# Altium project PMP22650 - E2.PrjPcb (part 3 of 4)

## Sheet PMP22650 CLLLC Power Stage.SchDoc
size 431 x 279 mm; Date: Not shown in title block; ApprovedBy: Not shown in title block; CheckedBy: Not shown in title block; Author: Not shown in title block; CompanyName: Not shown in title block; Engineer: Not shown in title block; Organization: Not shown in title block; Address1: Not shown in title block; Address2: Not shown in title block; Address3: Not shown in title block; Address4: Not shown in title block; DocumentNumber: 10; Revision: Use project parameter SCH_Rev; SheetNumber: 10; SheetTotal: 16; PageSetup: Record=PageOptions¦CenterHorizontal=True¦CenterVertical=True¦PrintScale=1.00¦XCorrection=1.00¦YCorrection=1.00¦PrintKind=0¦BorderSize=5000000¦LeftOffset=0¦BottomOffset=0¦Orientation=2¦PaperLength=1000¦PaperWidth=1000¦Scale=100¦PaperSource=15¦PrintQuality=600¦MediaType=1¦DitherType=10¦PaperKind=Letter¦PrintScaleMode=1
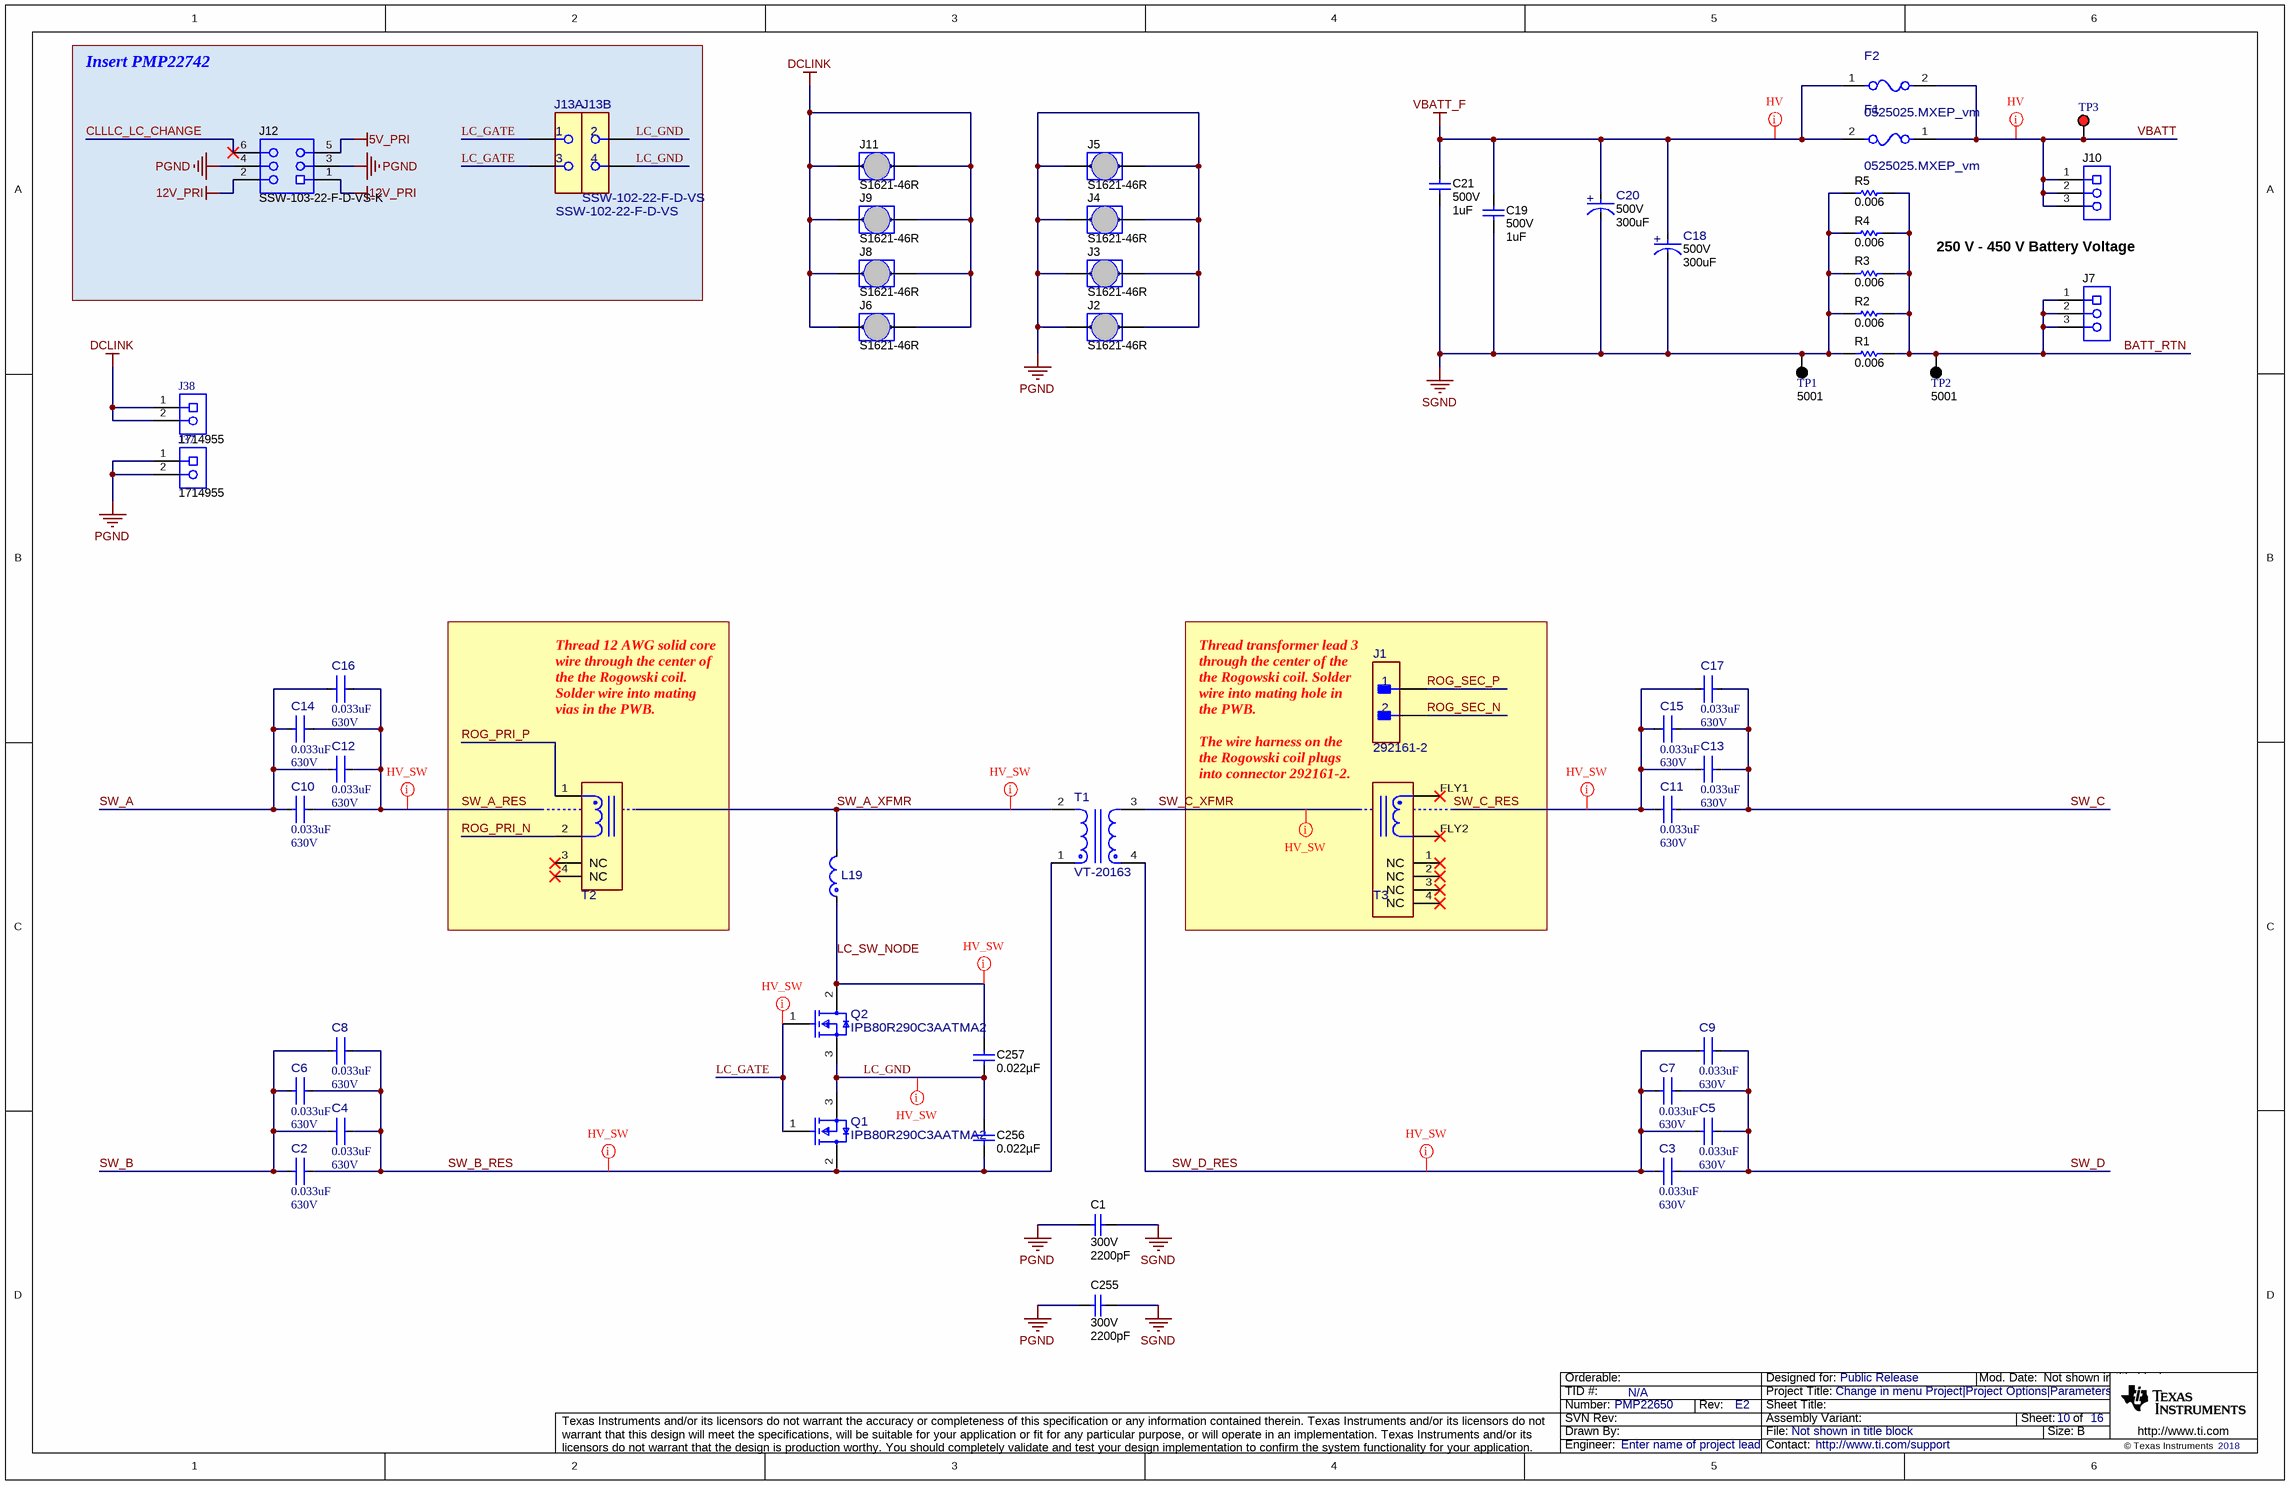
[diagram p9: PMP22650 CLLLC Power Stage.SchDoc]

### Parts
C1  VDC_V: 300V  ValueDisplayed: 2200pF  [AY2_950x500_Straight]  (hidden comment: AY2222M35Y5US63L7)
C2  ValueDisplayed: 0.033uF  VDC_V: 630V  [FP-C1210X333JBGACAUTO_1210-MFG]  (hidden comment: C1210X333JBGACAUTO)
C3  ValueDisplayed: 0.033uF  VDC_V: 630V  [FP-C1210X333JBGACAUTO_1210-MFG]  (hidden comment: C1210X333JBGACAUTO)
C4  ValueDisplayed: 0.033uF  VDC_V: 630V  [FP-C1210X333JBGACAUTO_1210-MFG]  (hidden comment: C1210X333JBGACAUTO)
C5  ValueDisplayed: 0.033uF  VDC_V: 630V  [FP-C1210X333JBGACAUTO_1210-MFG]  (hidden comment: C1210X333JBGACAUTO)
C6  ValueDisplayed: 0.033uF  VDC_V: 630V  [FP-C1210X333JBGACAUTO_1210-MFG]  (hidden comment: C1210X333JBGACAUTO)
C7  ValueDisplayed: 0.033uF  VDC_V: 630V  [FP-C1210X333JBGACAUTO_1210-MFG]  (hidden comment: C1210X333JBGACAUTO)
C8  ValueDisplayed: 0.033uF  VDC_V: 630V  [FP-C1210X333JBGACAUTO_1210-MFG]  (hidden comment: C1210X333JBGACAUTO)
C9  ValueDisplayed: 0.033uF  VDC_V: 630V  [FP-C1210X333JBGACAUTO_1210-MFG]  (hidden comment: C1210X333JBGACAUTO)
C10  ValueDisplayed: 0.033uF  VDC_V: 630V  [FP-C1210X333JBGACAUTO_1210-MFG]  (hidden comment: C1210X333JBGACAUTO)
C11  ValueDisplayed: 0.033uF  VDC_V: 630V  [FP-C1210X333JBGACAUTO_1210-MFG]  (hidden comment: C1210X333JBGACAUTO)
C12  ValueDisplayed: 0.033uF  VDC_V: 630V  [FP-C1210X333JBGACAUTO_1210-MFG]  (hidden comment: C1210X333JBGACAUTO)
C13  ValueDisplayed: 0.033uF  VDC_V: 630V  [FP-C1210X333JBGACAUTO_1210-MFG]  (hidden comment: C1210X333JBGACAUTO)
C14  ValueDisplayed: 0.033uF  VDC_V: 630V  [FP-C1210X333JBGACAUTO_1210-MFG]  (hidden comment: C1210X333JBGACAUTO)
C15  ValueDisplayed: 0.033uF  VDC_V: 630V  [FP-C1210X333JBGACAUTO_1210-MFG]  (hidden comment: C1210X333JBGACAUTO)
C16  ValueDisplayed: 0.033uF  VDC_V: 630V  [FP-C1210X333JBGACAUTO_1210-MFG]  (hidden comment: C1210X333JBGACAUTO)
C17  ValueDisplayed: 0.033uF  VDC_V: 630V  [FP-C1210X333JBGACAUTO_1210-MFG]  (hidden comment: C1210X333JBGACAUTO)
C18  VDC_V: 500V  ValueDisplayed: 300uF  [FP-ALA8DA301CF500_RADIAL-MFG]  (hidden comment: ALA8DA301CF500)
C19  VDC_V: 500V  ValueDisplayed: 1uF  [B58031I_1084x785x450]  (hidden comment: B58031I5105M002)
C20  VDC_V: 500V  ValueDisplayed: 300uF  [FP-ALA8DA301CF500_RADIAL-MFG]  (hidden comment: ALA8DA301CF500)
C21  VDC_V: 500V  ValueDisplayed: 1uF  [B58031I_1084x785x450]  (hidden comment: B58031I5105M002)
C255  VDC_V: 300V  ValueDisplayed: 2200pF  [AY2_950x500_Straight]  (hidden comment: AY2222M35Y5US63L7)
C256  ValueDisplayed: 0.022µF  [1206_190]  (hidden comment: C1206C223KDRACTU)
C257  ValueDisplayed: 0.022µF  [1206_190]  (hidden comment: C1206C223KDRACTU)
F1  0525025.MXEP_vm  [FP-0525025.MXEP_vm_AXIAL-MFG]
F2  0525025.MXEP_vm  [FP-0525025.MXEP_vm_AXIAL-MFG]
J1  292161-2  [FP-292161-2_HDR2-MFG]
J2  S1621-46R  [Harwin_S1621-46R]
J3  S1621-46R  [Harwin_S1621-46R]
J4  S1621-46R  [Harwin_S1621-46R]
J5  S1621-46R  [Harwin_S1621-46R]
J6  S1621-46R  [Harwin_S1621-46R]
J7  282856-3  [TE_282856-3]  (value not drawn)
J8  S1621-46R  [Harwin_S1621-46R]
J9  S1621-46R  [Harwin_S1621-46R]
J10  282856-3  [TE_282856-3]  (value not drawn)
J11  S1621-46R  [Harwin_S1621-46R]
J12  SSW-103-22-F-D-VS-K  [SAMTEC_SSW-103-22-F-D-VS-K]
J13  SSW-102-22-F-D-VS  [FP-SSW-102-22-F-D-VS_RCPT4-MFG]  (parts A,B of 2)
J37  1714955  [Phoenix_1714955]
J38  1714955  [Phoenix_1714955]
L19  VI-20173B  [FP-VI-20173B_PTH_INDUCTOR_34MM00_19MM00-MFG]  (value not drawn)
Q1  IPB80R290C3AATMA2  [FP-IPB80R290C3AATMA2_D2PAK-MFG]
Q2  IPB80R290C3AATMA2  [FP-IPB80R290C3AATMA2_D2PAK-MFG]
R1  ValueDisplayed: 0.006  [1206]  (hidden comment: WSL12066L000FEA18)
R2  ValueDisplayed: 0.006  [1206]  (hidden comment: WSL12066L000FEA18)
R3  ValueDisplayed: 0.006  [1206]  (hidden comment: WSL12066L000FEA18)
R4  ValueDisplayed: 0.006  [1206]  (hidden comment: WSL12066L000FEA18)
R5  ValueDisplayed: 0.006  [1206]  (hidden comment: WSL12066L000FEA18)
T1  VT-20163  [FP-VT-20163_PTH_TRANSFORMER_73MM0_51MM0-MFG]
T2  RLTI-1371  [FP-RLTI-1371_PTH_XFRMR_0IN828_0IN300-MFG]  (value not drawn)
T3  RLTI-1379  [FP-RLTI-1379_PTH_XFRMR_0IN828_0IN300-MFG]  (value not drawn)
TP1  5001  [Keystone5001]
TP2  5001  [Keystone5001]
TP3  5000  [Keystone5000]  (value not drawn)

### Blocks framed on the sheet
Insert PMP22742: J12 J13

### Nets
5V_PRI: J12.5
12V_PRI: J12.1 J12.2
DCLINK: J6.1 J6.2 J8.1 J8.2 J9.1 J9.2 J11.1 J11.2 J38.1 J38.2
PGND: C1.2 C255.2 J2.1 J2.2 J3.1 J3.2 J4.1 J4.2 J5.1 J5.2 J12.3 J12.4 J37.1 J37.2
SGND: C1.1 C18.1(CATHODE) C19.2 C20.1(CATHODE) C21.2 C255.1 R1.1 R2.1 R3.1 R4.1 R5.1 TP1.1
VBATT_F: C18.2(ANODE) C19.1 C20.2(ANODE) C21.1 F1.2 F2.1
BATT_RTN: J7.1 J7.2 J7.3 R1.2 R2.2 R3.2 R4.2 R5.2 TP2.1
CLLLC_LC_CHANGE: J12.6
LC_GATE: J13.1 J13.3 Q1.1(GATE) Q2.1(GATE)
LC_GND: C256.1 C257.2 J13.2 J13.4 Q1.3(SOURCE) Q2.3(SOURCE)
LC_SW_NODE: C257.1 L19.1 Q2.2(DRAIN)
ROG_PRI_N: T2.2
ROG_PRI_P: T2.1
ROG_SEC_N: J1.2
ROG_SEC_P: J1.1
SW_A: C10.2 C12.2 C14.2 C16.2
SW_A_RES: C10.1 C12.1 C14.1 C16.1
SW_A_XFMR: L19.2 T1.2
SW_B: C2.2 C4.2 C6.2 C8.2
SW_B_RES: C2.1 C4.1 C6.1 C8.1 C256.2 Q1.2(DRAIN) T1.1
SW_C: C11.2 C13.2 C15.2 C17.2
SW_C_RES: C11.1 C13.1 C15.1 C17.1
SW_C_XFMR: T1.3
SW_D: C3.1 C5.1 C7.1 C9.1
SW_D_RES: C3.2 C5.2 C7.2 C9.2 T1.4
VBATT: F1.1 F2.2 J10.1 J10.2 J10.3 TP3.1

Not connected (* = marked no-connect by the designer): T2 3(NC)* 4(NC)*; T3 1(NC)* 2(NC)* 3(NC)* 4(NC)*

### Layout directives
net class HV: VBATT, VBATT_F
net class HV_SW: LC_GATE, LC_GND, LC_SW_NODE, SW_A_RES, SW_A_XFMR, SW_B_RES, SW_C_RES, SW_C_XFMR, SW_D_RES

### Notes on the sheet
- 250 V - 450 V Battery Voltage
- Thread 12 AWG solid core wire through the center of the the Rogowski coil. Solder wire into mating vias in the PWB.
- (near J1) Thread transformer lead 3 through the center of the the Rogowski coil. Solder wire into mating hole in the PWB.
  The wire harness on the the Rogowski coil plugs into connector 292161-2.

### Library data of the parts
C1 C255 = CMP-0009587-2: CAP, CERM, 2200 pF, 300 V, +/- 20%, Y5U, AEC-Q200 Grade 1, D9.5xT5mm; Manufacturer: Vishay-Bccomponents; TaMin_C: -55°C; Polarized: N; SizeAreaWB_mm2: 80.5; Value1: Unknown; U/M: EA; Value: 2200pF; TaMax_C: 125°C; SizeZ_mm: 14.5; SizeX_mm: 9.5; SizeY_mm: 5; Cap_Case: 9.5x5mm; SizeArea_mm2: 47.5; AEC Qualified: Y; Cap_F: 2.2nF; AEC Grade: 1; AEC Category: Q200
C2-C17 = CMP-0090696-1: 0.033µF ±5% 630V Ceramic Capacitor C0G, NP0 1210 (3225 Metric); Manufacturer: Kemet; Cap_F: 33nF; SizeZ_mm: 2.8mm; TempCo: 30ppm/°C; AEC Qualified: Yes; Value: 33nF; AEC Grade: Grade 1
C18 C20 = CMP-0090464-1: 300µF 500V Aluminum Electrolytic Capacitors Radial, Can - Snap-In 687.4mOhm @ 100Hz 7000 Hrs @ 105°C; Manufacturer: Kemet; Tolerance_%: 20%; AEC Qualified: Yes; Esr: 0.687; Leakage Current: 450uA; Life: 11000Hours; AEC Grade: Grade 2; SizeZ_mm: 52mm; IRMS_A: 4.8A
C19 C21 = CMP-0009311-2: CAP, CERM, 1 uF, 500 V, +/- 20%, B58031, AEC-Q200 Grade 0, 6.84x7.85mm; Manufacturer: TDK; PartNumber: B58031I5105M062; TaMin_C: -40°C; Polarized: N; SizeAreaWB_mm2: 126.474; Value1: Unknown; U/M: EA; Value: 1uF; TaMax_C: 150°C; SizeZ_mm: 4.5; SizeX_mm: 10.84; SizeY_mm: 7.85; Cap_Case: 10.84x7.85x4.5mm; SizeArea_mm2: 85.094; CompType: Capacitor; AEC Qualified: Y; Cap_F: 1µF; IRMS_A: 7.5A; AEC Grade: 0; AEC Category: Q200
C256 C257 = CMP-0084048-1: CAP, CERM, 0.022 µF, 1000 V,+/- 10%, X7R, AEC-Q200 Grade 1, 1206; Manufacturer: Kemet; Polarized: N; CompType: Capacitor; Value: 0.022uF; U/M: EA; Cap_F: 22nF; VDC_V: 1kV; Value2: 1000V; TaMin_C: -55°C; TaMax_C: 125°C; Cap_Case: 1206; SizeArea_mm2: 5.12; SizeAreaWB_mm2: 10.92; SizeX_mm: 3.2; SizeY_mm: 1.6; SizeZ_mm: 1.9; AEC Category: Q200; AEC Qualified: Y; AEC Grade: 1
F1 F2 = CMP-4956-0000-1: 25A AC 450V DC Fuse Cartridge, Ceramic Through Hole 3AB, 3AG, 1/4" x 1-1/4" (Axial); Manufacturer: Littelfuse; AEC Grade: NA; Fuse Interrupt Dc Current: 10000A; AEC Qualified: No; Res_ohm: 3.8mΩ; MeltingTyp: 320A2Sec; Interrupt_DC: 10kA
J1 = CMP-0090793-1: Connector Header Through Hole 2 position 0.079" (2.00mm); Manufacturer: TE Connectivity; Current_A: 4A; Conn Orientation: Vertical; SizeZ_mm: 7mm; Conn Gender: Male; Row_Count: 1; DUT-Pitch_mm: 2mm; Voltage_V: 125V; ContactFinish: Tin,Nickel; AEC Qualified: No
J2-J6 J8 J9 J11 = CMP-0075177-1: JUMPER TIN SMD, SMT; Manufacturer: Harwin; CNHeader: False; Current_A: 10A; Green_Lifecycle: Active; Green_REACh: Passed; CompType: Jumper Wire
J7 J10 = CMP-0054983-1: Receptacle, 3x1, 5mm, R/A, TH; Manufacturer: On Shore Technology Inc.; PartNumber: ED700/3; CNHeader: FALSE; Current_A: 24A; Gender: Female; Voltage_V: 300V; CompType: Terminal Block; Row_Count: 1; Pitch_mm: 5; ContactFinish: Tin; CT: TRUE; Cert_UL: Y
J12 = CMP-0055666-1: Receptacle, 2.54mm, 3x2, Tin, SMT; Manufacturer: Samtec; CNHeader: FALSE; Current_A: 5.7A; Gender: Female; CompType: Socket Strip; Row_Count: 2; RowSpacing_mm: 2.54; ContactFinish: Gold; CT: TRUE; Cert_UL: Y
J13 = CMP-0090790-1: 4 Position Receptacle Connector  Surface Mount; Manufacturer: Samtec; Conn Gender: Female; SizeZ_mm: 10.21mm; DUT-Pitch_mm: 2.54mm; Is Female: yes; Voltage_V: 655V; Current_A: 4.7A; Row_Count: 2; AEC Qualified: No; ContactFinish: Gold,Nickel; Standoff Height: 0.97mm; Conn Orientation: Vertical
J37 J38 = CMP-0055505-1: Terminal Block, 2x1, 6.35mm, Green, TH; Manufacturer: Phoenix Contact; CNHeader: FALSE; Shrouded: Y; Gender: Female; Row_Count: 1; Pitch_mm: 6.35; CT: TRUE
L19 = CMP-0090978-1: OBC Resonant Inductor; Manufacturer: Cyntec; Ind_H: 50µH; Value: 50uH; Test Frequency: 500kHz; AEC Qualified: No; DCR_ohm: 69m
Q1 Q2 = CMP-0090447-1: N-Channel 800V 17A (Tc) 227W (Tc) Surface Mount PG-TO263-3-2; Manufacturer: Infineon Technologies; VdsMax_V: 1.2V; Reverse Recovery Time: 550ns; AEC Qualified: Yes; Number Of Channels: 1; Input Capacitace At Vds: 2300pF @ 100V; Turn Off Delay Time: 72ns; Rdson45_ohm: 0.25; Turn On Delay Time: 25ns; Threshold Vgs Max: 3.9V; Rthja Max: 62K/W; QgTyp_nC: 88nC @ 10V; Vgs_V: 20V; TJmax_C: +150°C; Pulse Drain Current: 51A; AEC Grade: Grade 0; Standoff Height: 0mm; Typ Forward Diode Voltage: 1V; Threshold Vgs Min: 2.1V; Reverse Recovery Charge: 15000nC; ChMode: False; SizeZ_mm: 4.7mm
R1-R5 = CMP-0018567-2: RES, 0.006, 1%, 0.5 W, 1206; Manufacturer: Vishay-Dale; Power_W: 500mW; TempCo: 110 ppm/C; Value_Code: 6L000; U/M: EA; Value: 0.006; EIA_Code: E96; Res_ohm: 6m; SizeX_mm: 3.2; SizeY_mm: 1.6; SizeZ_mm: 1.35; Value2: 0.5W; SizeArea_mm2: 5.12; AEC Category: Q200
T1 = CMP-0090781-3: TRANSFORMER; Manufacturer: Cyntec; DCR_ohm: 9.6m; Ind_H: 16µH; Voltage_Isolation_Vrms: 2000VDC; Rsec1_ohm: 7.4m; AEC Qualified: Unknown
T2 = CMP-0090959-1: PRIMARY SIDE ROGOWSKI (PMP22495); Manufacturer: Renco Electronics; SizeZ_mm: 0.938inch; AEC Qualified: No; Ind_H: 6.3µH; DCR_ohm: 1.2
T3 = CMP-0090960-2: Secondary Side Rogowski (PMP22495); Manufacturer: Renco Electronics; AEC Qualified: No; Ind_H: 6.3µH; SizeZ_mm: 0.938inch; DCR_ohm: 1.2
TP1 TP2 = CMP-0055138-1: Test Point, Miniature, Black, TH; Manufacturer: Keystone; CNHeader: FALSE; Green_Lifecycle: Active; Green_REACh: Passed; ContactFinish: Silver; CT: TRUE
TP3 = CMP-0055137-1: Test Point, Miniature, Red, TH; Manufacturer: Keystone; CNHeader: FALSE; Green_Lifecycle: Active; Green_REACh: Passed; ContactFinish: Silver; CT: TRUE

## Sheet PMP22650 CLLLC GaN Phase A.SchDoc
size 431 x 279 mm; Date: Not shown in title block; ApprovedBy: Not shown in title block; CheckedBy: Not shown in title block; Author: Not shown in title block; CompanyName: Not shown in title block; Engineer: Not shown in title block; Organization: Not shown in title block; Address1: Not shown in title block; Address2: Not shown in title block; Address3: Not shown in title block; Address4: Not shown in title block; DocumentNumber: 11; Revision: Use project parameter SCH_Rev; SheetNumber: 11; SheetTotal: 16; PageSetup: Record=PageOptions¦CenterHorizontal=True¦CenterVertical=True¦PrintScale=1.00¦XCorrection=1.00¦YCorrection=1.00¦PrintKind=0¦BorderSize=5000000¦LeftOffset=0¦BottomOffset=0¦Orientation=2¦PaperLength=1000¦PaperWidth=1000¦Scale=100¦PaperSource=15¦PrintQuality=600¦MediaType=1¦DitherType=10¦PaperKind=Letter¦PrintScaleMode=1
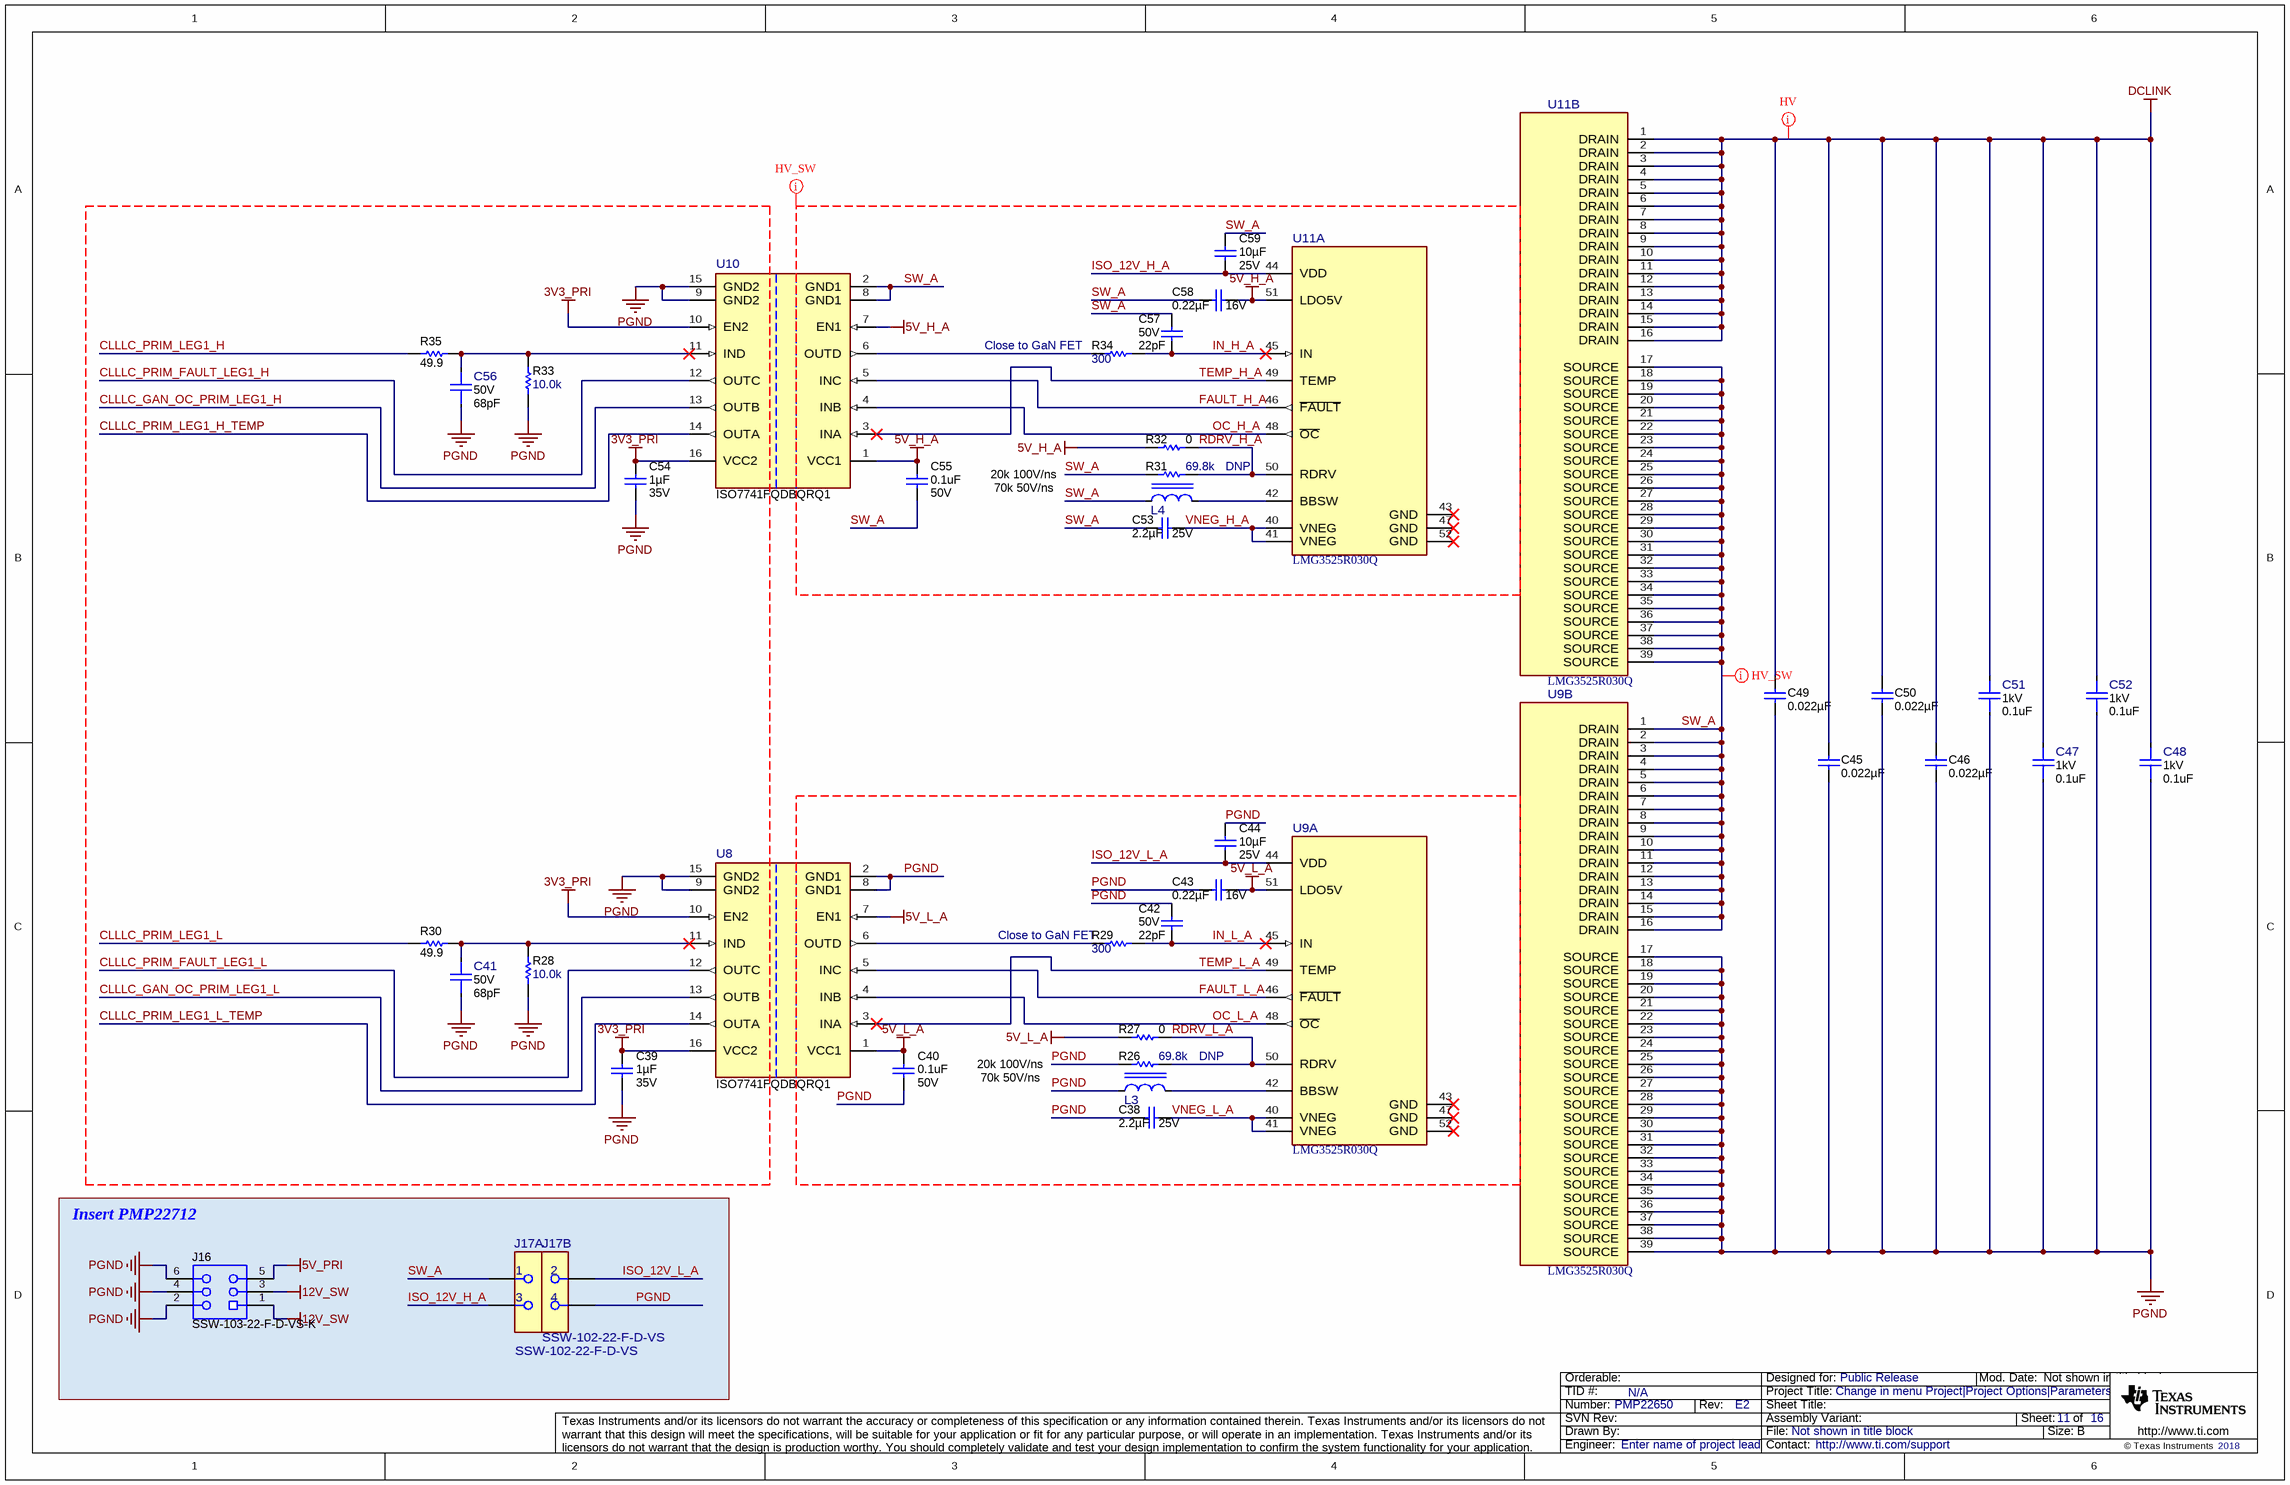
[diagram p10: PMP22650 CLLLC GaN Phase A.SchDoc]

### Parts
C38  Cap_F: 2.2µF  VDC_V: 25V  [0805_HV]  (hidden comment: CGA4J3X7R1E225K125AB)
C39  VDC_V: 35V  ValueDisplayed: 1µF  [0402]  (hidden comment: GRT155R6YA105KE13D)
C40  VDC_V: 50V  ValueDisplayed: 0.1uF  [0402]  (hidden comment: GCM155R71H104KE02D)
C41  VDC_V: 50V  ValueDisplayed: 68pF  [FP-GCM1555C1H680JA16D_0402-MFG]  (hidden comment: GCM1555C1H680JA16D)
C42  VDC_V: 50V  ValueDisplayed: 22pF  [0402]  (hidden comment: GCM1555C1H220JA16D)
C43  VDC_V: 16V  ValueDisplayed: 0.22µF  [0402]  (hidden comment: GCM155R71C224KE02D)
C44  VDC_V: 25V  ValueDisplayed: 10µF  [1206_180]  (hidden comment: TMK316AB7106KLHT)
C45  ValueDisplayed: 0.022µF  [1206_190]  (hidden comment: C1206C223KDRACTU)
C46  ValueDisplayed: 0.022µF  [1206_190]  (hidden comment: C1206C223KDRACTU)
C47  VDC_V: 1kV  ValueDisplayed: 0.1uF  [FP-C1812X104KDRACAUTO_1812-MFG]  (hidden comment: C1812X104KDRACAUTO)
C48  VDC_V: 1kV  ValueDisplayed: 0.1uF  [FP-C1812X104KDRACAUTO_1812-MFG]  (hidden comment: C1812X104KDRACAUTO)
C49  ValueDisplayed: 0.022µF  [1206_190]  (hidden comment: C1206C223KDRACTU)
C50  ValueDisplayed: 0.022µF  [1206_190]  (hidden comment: C1206C223KDRACTU)
C51  VDC_V: 1kV  ValueDisplayed: 0.1uF  [FP-C1812X104KDRACAUTO_1812-MFG]  (hidden comment: C1812X104KDRACAUTO)
C52  VDC_V: 1kV  ValueDisplayed: 0.1uF  [FP-C1812X104KDRACAUTO_1812-MFG]  (hidden comment: C1812X104KDRACAUTO)
C53  Cap_F: 2.2µF  VDC_V: 25V  [0805_HV]  (hidden comment: CGA4J3X7R1E225K125AB)
C54  VDC_V: 35V  ValueDisplayed: 1µF  [0402]  (hidden comment: GRT155R6YA105KE13D)
C55  VDC_V: 50V  ValueDisplayed: 0.1uF  [0402]  (hidden comment: GCM155R71H104KE02D)
C56  VDC_V: 50V  ValueDisplayed: 68pF  [FP-GCM1555C1H680JA16D_0402-MFG]  (hidden comment: GCM1555C1H680JA16D)
C57  VDC_V: 50V  ValueDisplayed: 22pF  [0402]  (hidden comment: GCM1555C1H220JA16D)
C58  VDC_V: 16V  ValueDisplayed: 0.22µF  [0402]  (hidden comment: GCM155R71C224KE02D)
C59  VDC_V: 25V  ValueDisplayed: 10µF  [1206_180]  (hidden comment: TMK316AB7106KLHT)
J16  SSW-103-22-F-D-VS-K  [SAMTEC_SSW-103-22-F-D-VS-K]
J17  SSW-102-22-F-D-VS  [FP-SSW-102-22-F-D-VS_RCPT4-MFG]  (parts A,B of 2)
L3  MPIA2510V2-4R7-R  [FP-MPIA2510V2-4R7-R_1008-MFG]  (value not drawn)
L4  MPIA2510V2-4R7-R  [FP-MPIA2510V2-4R7-R_1008-MFG]  (value not drawn)
R26  ValueDisplayed: 69.8k  [0402]  (hidden comment: CRCW040269K8FKED)
R27  ValueDisplayed: 0  [0402]  (hidden comment: ERJ-2GE0R00X)
R28  ValueDisplayed: 10.0k  [0402]  (hidden comment: CRCW040210K0FKED)
R29  ValueDisplayed: 300  [0402]  (hidden comment: CRCW0402300RJNED)
R30  ValueDisplayed: 49.9  [0402]  (hidden comment: CRCW040249R9FKED)
R31  ValueDisplayed: 69.8k  [0402]  (hidden comment: CRCW040269K8FKED)
R32  ValueDisplayed: 0  [0402]  (hidden comment: ERJ-2GE0R00X)
R33  ValueDisplayed: 10.0k  [0402]  (hidden comment: CRCW040210K0FKED)
R34  ValueDisplayed: 300  [0402]  (hidden comment: CRCW0402300RJNED)
R35  ValueDisplayed: 49.9  [0402]  (hidden comment: CRCW040249R9FKED)
U8  ISO7741FQDBQRQ1  [DBQ0016A-MFG]
U9  LMG3525R030Q  [RQS0052A-MFG]  (parts A,B of 2)
U10  ISO7741FQDBQRQ1  [DBQ0016A-MFG]
U11  LMG3525R030Q  [RQS0052A-MFG]  (parts A,B of 2)

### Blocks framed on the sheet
Insert PMP22712: J16 J17

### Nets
3V3_PRI: C39.1 C54.1 U8.10(EN2) U8.16(VCC2) U10.10(EN2) U10.16(VCC2)
5V_H_A: C55.1 C58.1 R32.2 U10.1(VCC1) U10.7(EN1) U11.51(LDO5V)
5V_L_A: C40.1 C43.1 R27.2 U8.1(VCC1) U8.7(EN1) U9.51(LDO5V)
5V_PRI: J16.5
12V_SW: J16.1 J16.3
DCLINK: C45.1 C46.1 C47.2 C48.2 C49.1 C50.1 C51.2 C52.2 U11.1(DRAIN) U11.2(DRAIN) U11.3(DRAIN) U11.4(DRAIN) U11.5(DRAIN) U11.6(DRAIN) U11.7(DRAIN) U11.8(DRAIN) U11.9(DRAIN) U11.10(DRAIN) U11.11(DRAIN) U11.12(DRAIN) U11.13(DRAIN) U11.14(DRAIN) U11.15(DRAIN) U11.16(DRAIN)
PGND: C38.1 C39.2 C40.2 C41.1 C42.1 C43.2 C44.2 C45.2 C46.2 C47.1 C48.1 C49.2 C50.2 C51.1 C52.1 C54.2 C56.1 J16.2 J16.4 J16.6 J17.4 L3.1 R26.1 R28.1 R33.1 U8.2(GND1) U8.8(GND1) U8.9(GND2) U8.15(GND2) U9.17(SOURCE) U9.18(SOURCE) U9.19(SOURCE) U9.20(SOURCE) U9.21(SOURCE) U9.22(SOURCE) U9.23(SOURCE) U9.24(SOURCE) U9.25(SOURCE) U9.26(SOURCE) U9.27(SOURCE) U9.28(SOURCE) U9.29(SOURCE) U9.30(SOURCE) U9.31(SOURCE) U9.32(SOURCE) U9.33(SOURCE) U9.34(SOURCE) U9.35(SOURCE) U9.36(SOURCE) U9.37(SOURCE) U9.38(SOURCE) U9.39(SOURCE) U10.9(GND2) U10.15(GND2)
CLLLC_GAN_OC_PRIM_LEG1_H: U10.13(OUTB)
CLLLC_GAN_OC_PRIM_LEG1_L: U8.13(OUTB)
CLLLC_PRIM_FAULT_LEG1_H: U10.12(OUTC)
CLLLC_PRIM_FAULT_LEG1_L: U8.12(OUTC)
CLLLC_PRIM_LEG1_H: R35.1
CLLLC_PRIM_LEG1_H_TEMP: U10.14(OUTA)
CLLLC_PRIM_LEG1_L: R30.1
CLLLC_PRIM_LEG1_L_TEMP: U8.14(OUTA)
FAULT_H_A: U10.5(INC) U11.46(~{FAULT})
FAULT_L_A: U8.5(INC) U9.46(~{FAULT})
IN_H_A: C57.2 R34.2 U11.45(IN)
IN_L_A: C42.2 R29.2 U9.45(IN)
ISO_12V_H_A: C59.1 J17.3 U11.44(VDD)
ISO_12V_L_A: C44.1 J17.2 U9.44(VDD)
OC_H_A: U10.4(INB) U11.48(~{OC})
OC_L_A: U8.4(INB) U9.48(~{OC})
RDRV_H_A: R31.2 R32.1 U11.50(RDRV)
RDRV_L_A: R26.2 R27.1 U9.50(RDRV)
SW_A: C53.1 C55.2 C57.1 C58.2 C59.2 J17.1 L4.1 R31.1 U9.1(DRAIN) U9.2(DRAIN) U9.3(DRAIN) U9.4(DRAIN) U9.5(DRAIN) U9.6(DRAIN) U9.7(DRAIN) U9.8(DRAIN) U9.9(DRAIN) U9.10(DRAIN) U9.11(DRAIN) U9.12(DRAIN) U9.13(DRAIN) U9.14(DRAIN) U9.15(DRAIN) U9.16(DRAIN) U10.2(GND1) U10.8(GND1) U11.17(SOURCE) U11.18(SOURCE) U11.19(SOURCE) U11.20(SOURCE) U11.21(SOURCE) U11.22(SOURCE) U11.23(SOURCE) U11.24(SOURCE) U11.25(SOURCE) U11.26(SOURCE) U11.27(SOURCE) U11.28(SOURCE) U11.29(SOURCE) U11.30(SOURCE) U11.31(SOURCE) U11.32(SOURCE) U11.33(SOURCE) U11.34(SOURCE) U11.35(SOURCE) U11.36(SOURCE) U11.37(SOURCE) U11.38(SOURCE) U11.39(SOURCE)
TEMP_H_A: U10.3(INA) U11.49(TEMP)
TEMP_L_A: U8.3(INA) U9.49(TEMP)
VNEG_H_A: C53.2 U11.40(VNEG) U11.41(VNEG)
VNEG_L_A: C38.2 U9.40(VNEG) U9.41(VNEG)
NetC41_2: C41.2 R28.2 R30.2 U8.11(IND)
NetC56_2: C56.2 R33.2 R35.2 U10.11(IND)
NetL3_2: L3.2 U9.42(BBSW)
NetL4_2: L4.2 U11.42(BBSW)
NetR29_1: R29.1 U8.6(OUTD)
NetR34_1: R34.1 U10.6(OUTD)

Not connected (* = marked no-connect by the designer): U9 43(GND)* 47(GND)* 52(GND)*; U11 43(GND)* 47(GND)* 52(GND)*

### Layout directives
net class HV_SW: 5V_H_A, FAULT_H_A, IN_H_A, ISO_12V_H_A, OC_H_A, RDRV_H_A, SW_A, TEMP_H_A, VNEG_H_A
net class HV: DCLINK

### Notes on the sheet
- (near R34) Close to GaN FET
- 20k 100V/ns
- 70k 50V/ns
- DNP
- (near R29) Close to GaN FET

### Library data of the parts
C38 C53 = CMP-0007975-2: CAP, CERM, 2.2 uF, 25 V, +/- 10%, X7R, AEC-Q200 Grade 1, 0805; Manufacturer: TDK; TaMin_C: -55°C; Polarized: N; SizeAreaWB_mm2: 6.75; Value1: Unknown; U/M: EA; Value: 2.2uF; TaMax_C: 125°C; SizeZ_mm: 1.45; SizeX_mm: 2; SizeY_mm: 1.25; Cap_Case: 0805; SizeArea_mm2: 2.5; AEC Qualified: Y; AEC Grade: 1; AEC Category: Q200
C39 C54 = CMP-0750099-1: CAP, CERM, 1 µF, 35 V,+/- 10%, X5R, AEC-Q200 Grade 3, 0402; Manufacturer: MuRata; AEC Grade: 3; AEC Category: Q200; Value: 1uF; SizeArea_mm2: 0.5; SizeZ_mm: 0.6; AEC Qualified: Y; TaMin_C: -55°C; SizeX_mm: 1; U/M: EA; Polarized: N; TaMax_C: 85°C
C40 C55 = CMP-0006356-2: CAP, CERM, 0.1 uF, 50 V, +/- 10%, X7R, AEC-Q200 Grade 1, 0402; Manufacturer: MuRata; TaMin_C: -55°C; Polarized: N; SizeAreaWB_mm2: 3; Value1: Unknown; U/M: EA; Value: 0.1uF; TaMax_C: 125°C; SizeZ_mm: 0.6; SizeX_mm: 1; SizeY_mm: 0.5; AEC Qualified: Y; Cap_F: 100nF; AEC Category: Q200
C41 C56 = CMP-0090521-1: 68pF ±5% 50V Ceramic Capacitor C0G, NP0 0402 (1005 Metric); Manufacturer: Murata; AEC Qualified: Yes; AEC Grade: Grade 1; TempCo: 30ppm/°C; SizeZ_mm: 0.55mm
C42 C57 = CMP-0006348-2: CAP, CERM, 22 pF, 50 V, +/- 5%, C0G/NP0, AEC-Q200 Grade 1, 0402; Manufacturer: MuRata; TaMin_C: -55°C; Polarized: N; SizeAreaWB_mm2: 3; Value1: Unknown; U/M: EA; Value: 22pF; TaMax_C: 125°C; SizeZ_mm: 0.6; SizeX_mm: 1; SizeY_mm: 0.5; AEC Qualified: Y; AEC Category: Q200
C43 C58 = CMP-0078265-1: CAP, CERM, 0.22 µF, 16 V,+/- 10%, X7R, AEC-Q200 Grade 1, 0402; Manufacturer: MuRata; TaMin_C: -55°C; Polarized: N; SizeAreaWB_mm2: 3; U/M: EA; Value: 0.22uF; TaMax_C: 125°C; SizeZ_mm: 0.6; SizeX_mm: 1; SizeY_mm: 0.5; AEC Qualified: Y; Cap_F: 220nF; AEC Category: Q200
C44 C59 = CMP-0750154-1: CAP, CERM, 10 µF, 25 V,+/- 10%, X7R, AEC-Q200 Grade 1, 1206; Manufacturer: Taiyo Yuden; AEC Qualified: Y; SizeZ_mm: 1.8; TaMax_C: 125°C; TaMin_C: -55°C; Cap_Case: 1206; Polarized: N; AEC Grade: 1; SizeY_mm: 1.6; Value: 10uF; SizeX_mm: 3.2; SizeAreaWB_mm2: 10.92; AEC Category: Q200; U/M: EA; SizeArea_mm2: 5.12
C45 C46 C49 C50 = CMP-0084048-1: as C256 on sheet PMP22650 CLLLC Power Stage
C47 C48 C51 C52 = CMP-0090548-1: 0.1µF ±10% 1000V (1kV) Ceramic Capacitor X7R 1812 (4532 Metric); Manufacturer: Kemet; SizeZ_mm: 1.85mm; AEC Qualified: Yes; Cap_F: 100nF; TempCo: 15%; Value: 100nF; AEC Grade: Grade 1
J16 = CMP-0055666-1: as J12 on sheet PMP22650 CLLLC Power Stage
J17 = CMP-0090790-1: 4 Position Receptacle Connector  Surface Mount; Manufacturer: Samtec; DUT-Pitch_mm: 2.54mm; SizeZ_mm: 10.21mm; Current_A: 4.7A; ContactFinish: Gold,Nickel; Conn Gender: Female; Voltage_V: 655V; Is Female: yes; AEC Qualified: No; Row_Count: 2; Conn Orientation: Vertical; Standoff Height: 0.97mm
L3 L4 = CMP-0090507-1: 4.7µH Shielded Molded Inductor 1.22A 262mOhm Max 1008 (2520 Metric); Manufacturer: Eaton; Material: Metal Composite; Value: 4.7uH; Test Frequency: 1MHz; Isat: 1.8A; DCR_ohm: 0.262; AEC Grade: Grade 1; Tolerance_%: 20%; AEC Qualified: Yes; Self Resonant Frequency: 25MHz; SizeZ_mm: 1.05mm; Shrouded: true
R26 R31 = CMP-0026510-2: RES, 69.8 k, 1%, 0.063 W, AEC-Q200 Grade 0, 0402; Manufacturer: Vishay-Dale; Power_W: 63mW; TempCo: 100 ppm/C; Value_Code: 69k8; Value: 69.8k; EIA_Code: E96; SizeX_mm: 1; SizeY_mm: 0.5; SizeZ_mm: 0.6; Value2: 0.063W; AEC Qualified: Y; VDC_V: 50V; AEC Category: Q200; AEC Grade: 0
R27 R32 = CMP-0026992-3: RES, 0, 5%, 0.1 W, AEC-Q200 Grade 0, 0402; Manufacturer: Panasonic; Power_W: 100mW; TempCo: 600 ppm/C; Value_Code: 0000; Value: 0; EIA_Code: E24; SizeX_mm: 1; SizeY_mm: 0.5; SizeZ_mm: 0.6; Value2: 0.1W; AEC Qualified: Y; VDC_V: 50V; AEC Category: Q200; SizeAreaWB_mm2: 3
R28 R33 = CMP-0025958-3: RES, 10.0 k, 1%, 0.063 W, AEC-Q200 Grade 0, 0402; Manufacturer: Vishay-Dale; Power_W: 63mW; TempCo: 100 ppm/C; Value_Code: 10k0; Value: 10.0k; EIA_Code: E96; Res_ohm: 10k; SizeX_mm: 1; SizeY_mm: 0.5; SizeZ_mm: 0.6; Value2: 0.063W; AEC Qualified: Y; VDC_V: 50V; AEC Category: Q200; AEC Grade: 0
R29 R34 = CMP-0026902-3: RES, 300, 5%, 0.063 W, AEC-Q200 Grade 0, 0402; Manufacturer: Vishay-Dale; Power_W: 63mW; TempCo: 200 ppm/C; Value_Code: 300R; Value: 300; EIA_Code: E24; SizeX_mm: 1; SizeY_mm: 0.5; SizeZ_mm: 0.6; Value2: 0.063W; AEC Qualified: Y; VDC_V: 50V; AEC Category: Q200; AEC Grade: 0
R30 R35 = CMP-0026404-2: RES, 49.9, 1%, 0.063 W, AEC-Q200 Grade 0, 0402; Manufacturer: Vishay-Dale; Power_W: 63mW; TempCo: 100 ppm/C; Value_Code: 49R9; Value: 49.9; EIA_Code: E96; SizeX_mm: 1; SizeY_mm: 0.5; SizeZ_mm: 0.6; Value2: 0.063W; AEC Qualified: Y; VDC_V: 50V; AEC Category: Q200; AEC Grade: 0
U8 U10 = CMP-0090469-1: Manufacturer: Texas Instruments; TaMin_C: -40°C; TaMax_C: +125°C; TJmax_C: +150°C; AEC Grade: Grade 1; Min Supply Voltage: 2.25V; AEC Qualified: Yes; Max Supply Voltage: 5.5V; Standoff Height: 0.11mm; Nominal Supply Current: 1.5-18mA; SizeZ_mm: 1.75mm
U9 U11 = CMP-0089968-2: 650-V 30-mΩ GaN FET with Integrated Driver and Protection; Manufacturer: Texas Instruments; Output Voltage: 520V; Nominal Supply Current: 540uA; Min Supply Voltage: 7.5V; Standoff Height: 0mm; AEC Grade: Grade 1; Max Supply Voltage: 18V; Number Of Outputs: 1; AEC Qualified: Yes; TJmax_C: +125°C; SizeZ_mm: 1mm; AEC Category: Q200; CompType: IC

## Sheet PMP22650 CLLLC GaN Phase B.SchDoc
size 431 x 279 mm; Date: Not shown in title block; ApprovedBy: Not shown in title block; CheckedBy: Not shown in title block; Author: Not shown in title block; CompanyName: Not shown in title block; Engineer: Not shown in title block; Organization: Not shown in title block; Address1: Not shown in title block; Address2: Not shown in title block; Address3: Not shown in title block; Address4: Not shown in title block; DocumentNumber: 12; Revision: Use project parameter SCH_Rev; SheetNumber: 12; SheetTotal: 16; PageSetup: Record=PageOptions¦CenterHorizontal=True¦CenterVertical=True¦PrintScale=1.00¦XCorrection=1.00¦YCorrection=1.00¦PrintKind=0¦BorderSize=5000000¦LeftOffset=0¦BottomOffset=0¦Orientation=2¦PaperLength=1000¦PaperWidth=1000¦Scale=100¦PaperSource=15¦PrintQuality=600¦MediaType=1¦DitherType=10¦PaperKind=Letter¦PrintScaleMode=1
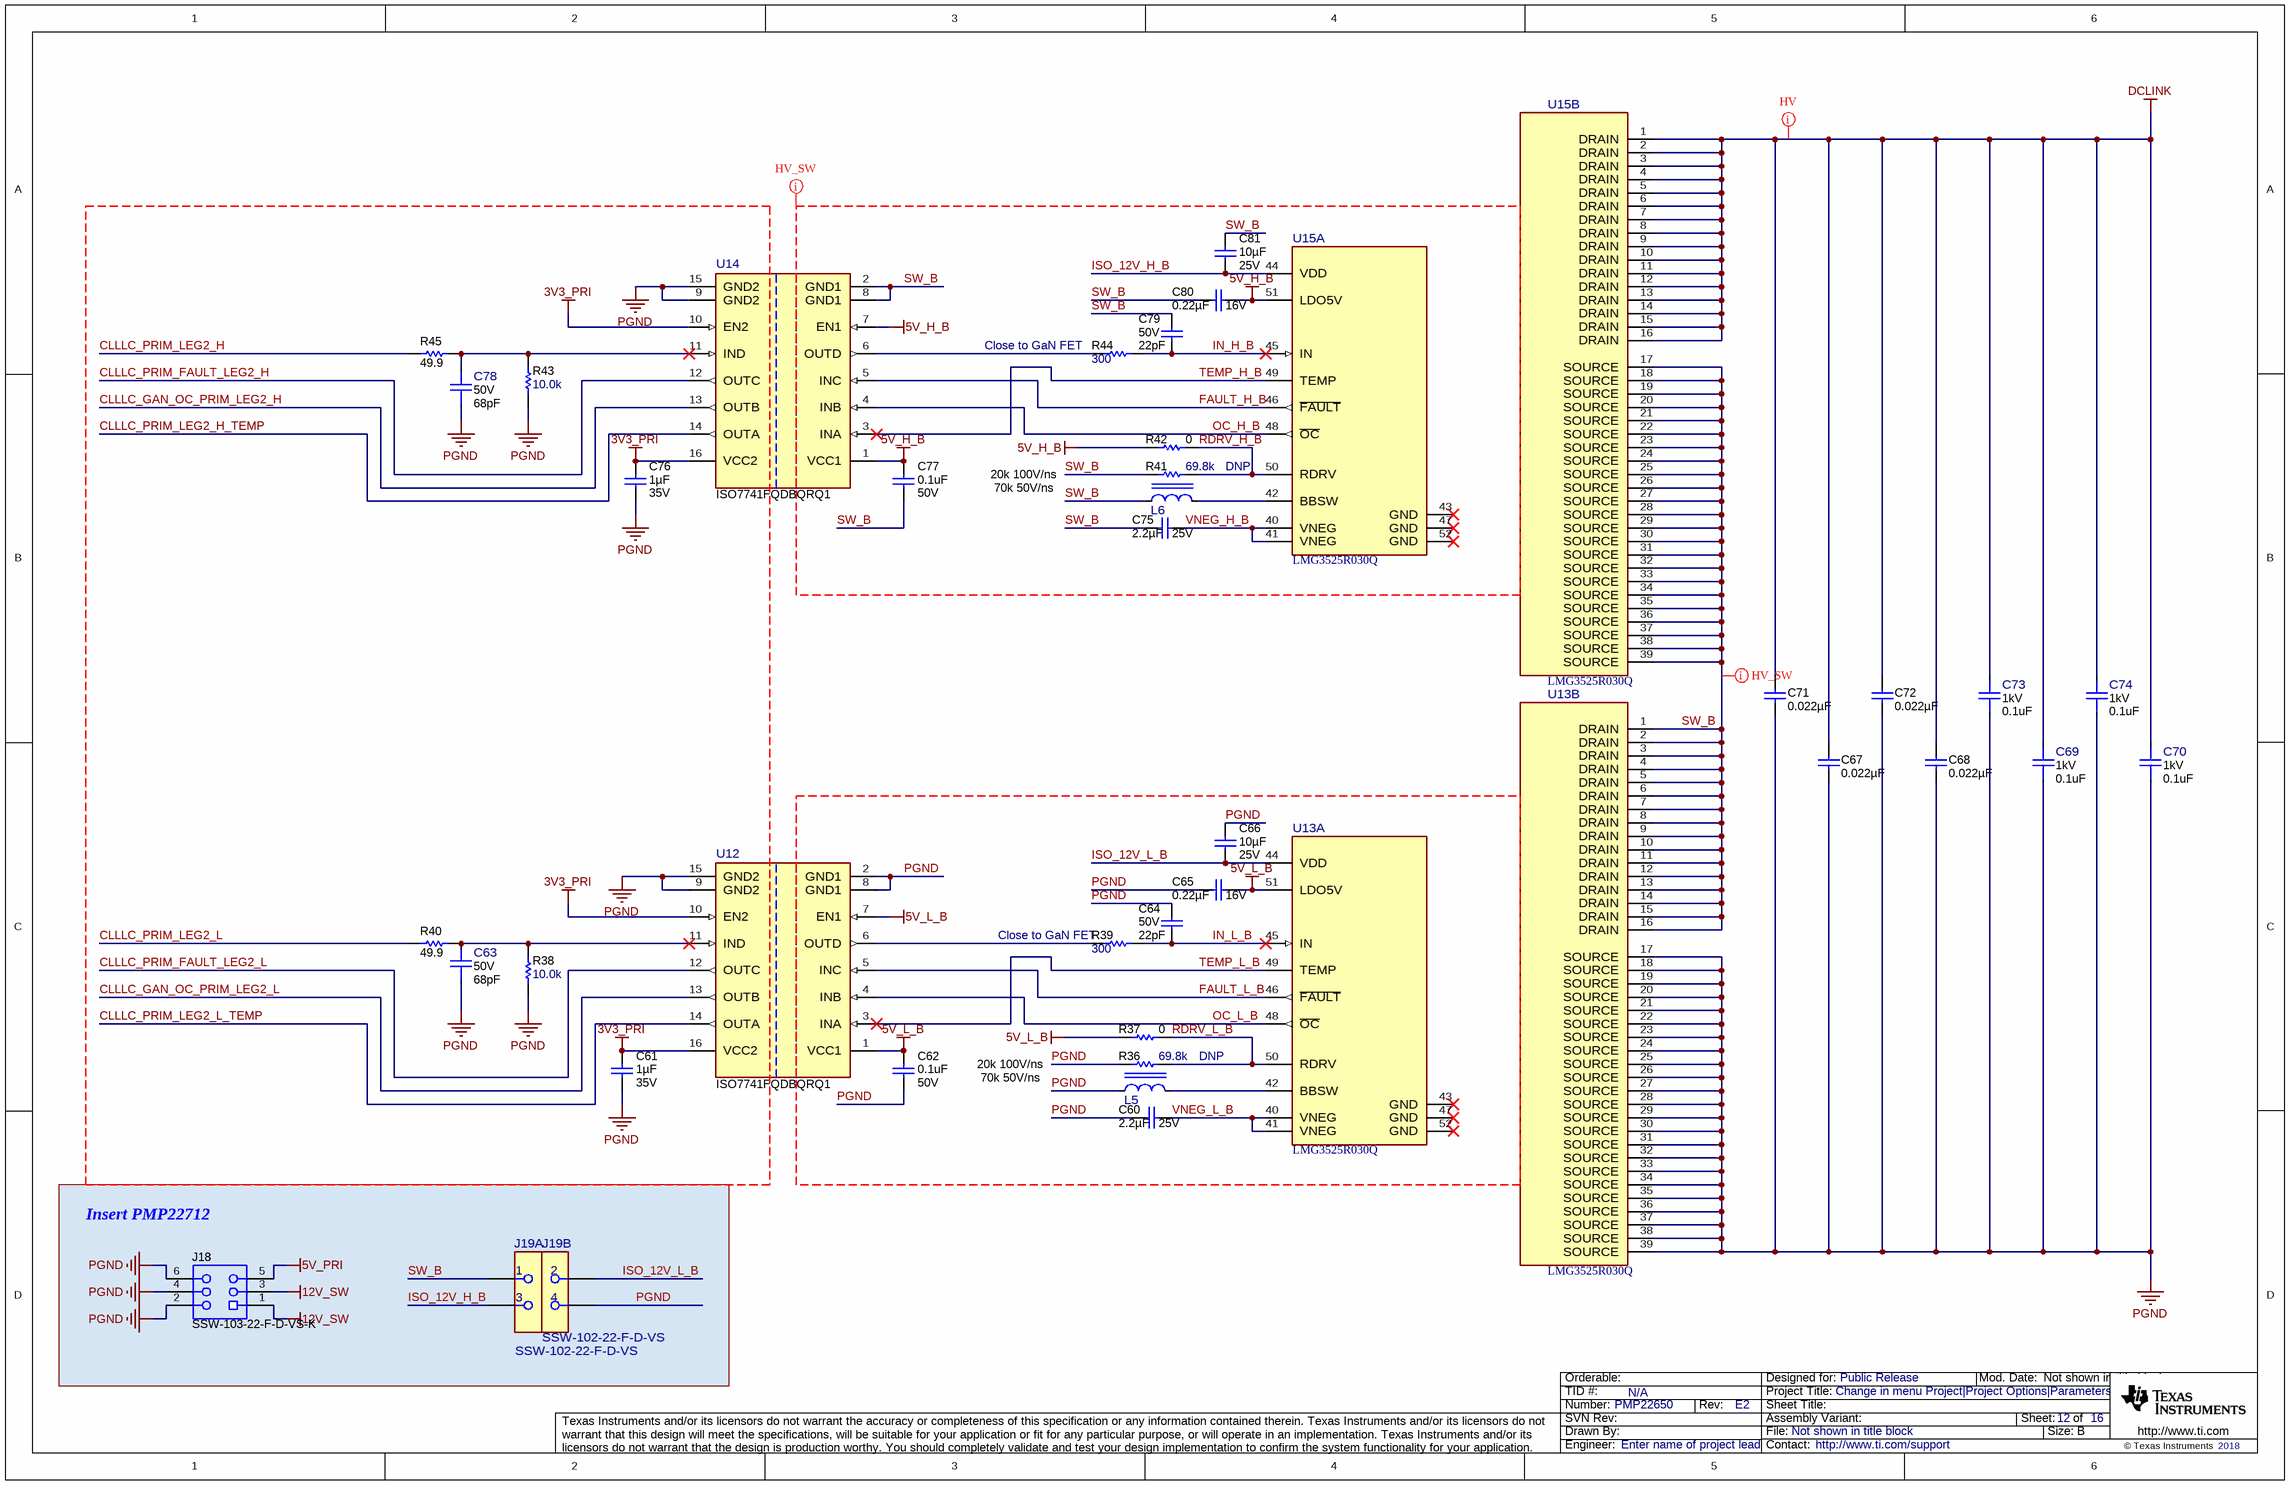
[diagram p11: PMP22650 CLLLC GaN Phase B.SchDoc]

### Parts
C60  Cap_F: 2.2µF  VDC_V: 25V  [0805_HV]  (hidden comment: CGA4J3X7R1E225K125AB)
C61  VDC_V: 35V  ValueDisplayed: 1µF  [0402]  (hidden comment: GRT155R6YA105KE13D)
C62  VDC_V: 50V  ValueDisplayed: 0.1uF  [0402]  (hidden comment: GCM155R71H104KE02D)
C63  VDC_V: 50V  ValueDisplayed: 68pF  [FP-GCM1555C1H680JA16D_0402-MFG]  (hidden comment: GCM1555C1H680JA16D)
C64  VDC_V: 50V  ValueDisplayed: 22pF  [0402]  (hidden comment: GCM1555C1H220JA16D)
C65  VDC_V: 16V  ValueDisplayed: 0.22µF  [0402]  (hidden comment: GCM155R71C224KE02D)
C66  VDC_V: 25V  ValueDisplayed: 10µF  [1206_180]  (hidden comment: TMK316AB7106KLHT)
C67  ValueDisplayed: 0.022µF  [1206_190]  (hidden comment: C1206C223KDRACTU)
C68  ValueDisplayed: 0.022µF  [1206_190]  (hidden comment: C1206C223KDRACTU)
C69  VDC_V: 1kV  ValueDisplayed: 0.1uF  [FP-C1812X104KDRACAUTO_1812-MFG]  (hidden comment: C1812X104KDRACAUTO)
C70  VDC_V: 1kV  ValueDisplayed: 0.1uF  [FP-C1812X104KDRACAUTO_1812-MFG]  (hidden comment: C1812X104KDRACAUTO)
C71  ValueDisplayed: 0.022µF  [1206_190]  (hidden comment: C1206C223KDRACTU)
C72  ValueDisplayed: 0.022µF  [1206_190]  (hidden comment: C1206C223KDRACTU)
C73  VDC_V: 1kV  ValueDisplayed: 0.1uF  [FP-C1812X104KDRACAUTO_1812-MFG]  (hidden comment: C1812X104KDRACAUTO)
C74  VDC_V: 1kV  ValueDisplayed: 0.1uF  [FP-C1812X104KDRACAUTO_1812-MFG]  (hidden comment: C1812X104KDRACAUTO)
C75  Cap_F: 2.2µF  VDC_V: 25V  [0805_HV]  (hidden comment: CGA4J3X7R1E225K125AB)
C76  VDC_V: 35V  ValueDisplayed: 1µF  [0402]  (hidden comment: GRT155R6YA105KE13D)
C77  VDC_V: 50V  ValueDisplayed: 0.1uF  [0402]  (hidden comment: GCM155R71H104KE02D)
C78  VDC_V: 50V  ValueDisplayed: 68pF  [FP-GCM1555C1H680JA16D_0402-MFG]  (hidden comment: GCM1555C1H680JA16D)
C79  VDC_V: 50V  ValueDisplayed: 22pF  [0402]  (hidden comment: GCM1555C1H220JA16D)
C80  VDC_V: 16V  ValueDisplayed: 0.22µF  [0402]  (hidden comment: GCM155R71C224KE02D)
C81  VDC_V: 25V  ValueDisplayed: 10µF  [1206_180]  (hidden comment: TMK316AB7106KLHT)
J18  SSW-103-22-F-D-VS-K  [SAMTEC_SSW-103-22-F-D-VS-K]
J19  SSW-102-22-F-D-VS  [FP-SSW-102-22-F-D-VS_RCPT4-MFG]  (parts A,B of 2)
L5  MPIA2510V2-4R7-R  [FP-MPIA2510V2-4R7-R_1008-MFG]  (value not drawn)
L6  MPIA2510V2-4R7-R  [FP-MPIA2510V2-4R7-R_1008-MFG]  (value not drawn)
R36  ValueDisplayed: 69.8k  [0402]  (hidden comment: CRCW040269K8FKED)
R37  ValueDisplayed: 0  [0402]  (hidden comment: ERJ-2GE0R00X)
R38  ValueDisplayed: 10.0k  [0402]  (hidden comment: CRCW040210K0FKED)
R39  ValueDisplayed: 300  [0402]  (hidden comment: CRCW0402300RJNED)
R40  ValueDisplayed: 49.9  [0402]  (hidden comment: CRCW040249R9FKED)
R41  ValueDisplayed: 69.8k  [0402]  (hidden comment: CRCW040269K8FKED)
R42  ValueDisplayed: 0  [0402]  (hidden comment: ERJ-2GE0R00X)
R43  ValueDisplayed: 10.0k  [0402]  (hidden comment: CRCW040210K0FKED)
R44  ValueDisplayed: 300  [0402]  (hidden comment: CRCW0402300RJNED)
R45  ValueDisplayed: 49.9  [0402]  (hidden comment: CRCW040249R9FKED)
U12  ISO7741FQDBQRQ1  [DBQ0016A-MFG]
U13  LMG3525R030Q  [RQS0052A-MFG]  (parts A,B of 2)
U14  ISO7741FQDBQRQ1  [DBQ0016A-MFG]
U15  LMG3525R030Q  [RQS0052A-MFG]  (parts A,B of 2)

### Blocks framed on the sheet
Insert PMP22712: J18 J19

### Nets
3V3_PRI: C61.1 C76.1 U12.10(EN2) U12.16(VCC2) U14.10(EN2) U14.16(VCC2)
5V_H_B: C77.1 C80.1 R42.2 U14.1(VCC1) U14.7(EN1) U15.51(LDO5V)
5V_L_B: C62.1 C65.1 R37.2 U12.1(VCC1) U12.7(EN1) U13.51(LDO5V)
5V_PRI: J18.5
12V_SW: J18.1 J18.3
DCLINK: C67.1 C68.1 C69.2 C70.2 C71.1 C72.1 C73.2 C74.2 U15.1(DRAIN) U15.2(DRAIN) U15.3(DRAIN) U15.4(DRAIN) U15.5(DRAIN) U15.6(DRAIN) U15.7(DRAIN) U15.8(DRAIN) U15.9(DRAIN) U15.10(DRAIN) U15.11(DRAIN) U15.12(DRAIN) U15.13(DRAIN) U15.14(DRAIN) U15.15(DRAIN) U15.16(DRAIN)
PGND: C60.1 C61.2 C62.2 C63.1 C64.1 C65.2 C66.2 C67.2 C68.2 C69.1 C70.1 C71.2 C72.2 C73.1 C74.1 C76.2 C78.1 J18.2 J18.4 J18.6 J19.4 L5.1 R36.1 R38.1 R43.1 U12.2(GND1) U12.8(GND1) U12.9(GND2) U12.15(GND2) U13.17(SOURCE) U13.18(SOURCE) U13.19(SOURCE) U13.20(SOURCE) U13.21(SOURCE) U13.22(SOURCE) U13.23(SOURCE) U13.24(SOURCE) U13.25(SOURCE) U13.26(SOURCE) U13.27(SOURCE) U13.28(SOURCE) U13.29(SOURCE) U13.30(SOURCE) U13.31(SOURCE) U13.32(SOURCE) U13.33(SOURCE) U13.34(SOURCE) U13.35(SOURCE) U13.36(SOURCE) U13.37(SOURCE) U13.38(SOURCE) U13.39(SOURCE) U14.9(GND2) U14.15(GND2)
CLLLC_GAN_OC_PRIM_LEG2_H: U14.13(OUTB)
CLLLC_GAN_OC_PRIM_LEG2_L: U12.13(OUTB)
CLLLC_PRIM_FAULT_LEG2_H: U14.12(OUTC)
CLLLC_PRIM_FAULT_LEG2_L: U12.12(OUTC)
CLLLC_PRIM_LEG2_H: R45.1
CLLLC_PRIM_LEG2_H_TEMP: U14.14(OUTA)
CLLLC_PRIM_LEG2_L: R40.1
CLLLC_PRIM_LEG2_L_TEMP: U12.14(OUTA)
FAULT_H_B: U14.5(INC) U15.46(~{FAULT})
FAULT_L_B: U12.5(INC) U13.46(~{FAULT})
IN_H_B: C79.2 R44.2 U15.45(IN)
IN_L_B: C64.2 R39.2 U13.45(IN)
ISO_12V_H_B: C81.1 J19.3 U15.44(VDD)
ISO_12V_L_B: C66.1 J19.2 U13.44(VDD)
OC_H_B: U14.4(INB) U15.48(~{OC})
OC_L_B: U12.4(INB) U13.48(~{OC})
RDRV_H_B: R41.2 R42.1 U15.50(RDRV)
RDRV_L_B: R36.2 R37.1 U13.50(RDRV)
SW_B: C75.1 C77.2 C79.1 C80.2 C81.2 J19.1 L6.1 R41.1 U13.1(DRAIN) U13.2(DRAIN) U13.3(DRAIN) U13.4(DRAIN) U13.5(DRAIN) U13.6(DRAIN) U13.7(DRAIN) U13.8(DRAIN) U13.9(DRAIN) U13.10(DRAIN) U13.11(DRAIN) U13.12(DRAIN) U13.13(DRAIN) U13.14(DRAIN) U13.15(DRAIN) U13.16(DRAIN) U14.2(GND1) U14.8(GND1) U15.17(SOURCE) U15.18(SOURCE) U15.19(SOURCE) U15.20(SOURCE) U15.21(SOURCE) U15.22(SOURCE) U15.23(SOURCE) U15.24(SOURCE) U15.25(SOURCE) U15.26(SOURCE) U15.27(SOURCE) U15.28(SOURCE) U15.29(SOURCE) U15.30(SOURCE) U15.31(SOURCE) U15.32(SOURCE) U15.33(SOURCE) U15.34(SOURCE) U15.35(SOURCE) U15.36(SOURCE) U15.37(SOURCE) U15.38(SOURCE) U15.39(SOURCE)
TEMP_H_B: U14.3(INA) U15.49(TEMP)
TEMP_L_B: U12.3(INA) U13.49(TEMP)
VNEG_H_B: C75.2 U15.40(VNEG) U15.41(VNEG)
VNEG_L_B: C60.2 U13.40(VNEG) U13.41(VNEG)
NetC63_2: C63.2 R38.2 R40.2 U12.11(IND)
NetC78_2: C78.2 R43.2 R45.2 U14.11(IND)
NetL5_2: L5.2 U13.42(BBSW)
NetL6_2: L6.2 U15.42(BBSW)
NetR39_1: R39.1 U12.6(OUTD)
NetR44_1: R44.1 U14.6(OUTD)

Not connected (* = marked no-connect by the designer): U13 43(GND)* 47(GND)* 52(GND)*; U15 43(GND)* 47(GND)* 52(GND)*

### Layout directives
net class HV_SW: 5V_H_B, FAULT_H_B, IN_H_B, ISO_12V_H_B, OC_H_B, RDRV_H_B, SW_B, TEMP_H_B, VNEG_H_B
net class HV: DCLINK

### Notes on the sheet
- (near R44) Close to GaN FET
- 20k 100V/ns
- 70k 50V/ns
- DNP
- (near R39) Close to GaN FET

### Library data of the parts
C60 C75 = CMP-0007975-2: as C38 on sheet PMP22650 CLLLC GaN Phase A
C61 C76 = CMP-0750099-1: as C39 on sheet PMP22650 CLLLC GaN Phase A
C62 C77 = CMP-0006356-2: as C40 on sheet PMP22650 CLLLC GaN Phase A
C63 C78 = CMP-0090521-1: as C41 on sheet PMP22650 CLLLC GaN Phase A
C64 C79 = CMP-0006348-2: as C42 on sheet PMP22650 CLLLC GaN Phase A
C65 C80 = CMP-0078265-1: as C43 on sheet PMP22650 CLLLC GaN Phase A
C66 C81 = CMP-0750154-1: as C44 on sheet PMP22650 CLLLC GaN Phase A
C67 C68 C71 C72 = CMP-0084048-1: as C256 on sheet PMP22650 CLLLC Power Stage
C69 C70 C73 C74 = CMP-0090548-1: as C47 on sheet PMP22650 CLLLC GaN Phase A
J18 = CMP-0055666-1: as J12 on sheet PMP22650 CLLLC Power Stage
J19 = CMP-0090790-1: as J17 on sheet PMP22650 CLLLC GaN Phase A
L5 L6 = CMP-0090507-1: as L3 on sheet PMP22650 CLLLC GaN Phase A
R36 R41 = CMP-0026510-2: as R26 on sheet PMP22650 CLLLC GaN Phase A
R37 R42 = CMP-0026992-3: as R27 on sheet PMP22650 CLLLC GaN Phase A
R38 R43 = CMP-0025958-3: as R28 on sheet PMP22650 CLLLC GaN Phase A
R39 R44 = CMP-0026902-3: as R29 on sheet PMP22650 CLLLC GaN Phase A
R40 R45 = CMP-0026404-2: as R30 on sheet PMP22650 CLLLC GaN Phase A
U12 U14 = CMP-0090469-1: as U8 on sheet PMP22650 CLLLC GaN Phase A
U13 U15 = CMP-0089968-2: as U9 on sheet PMP22650 CLLLC GaN Phase A

## Sheet PMP22650 CLLLC GaN Phase C.SchDoc
size 431 x 279 mm; Date: Not shown in title block; ApprovedBy: Not shown in title block; CheckedBy: Not shown in title block; Author: Not shown in title block; CompanyName: Not shown in title block; Engineer: Not shown in title block; Organization: Not shown in title block; Address1: Not shown in title block; Address2: Not shown in title block; Address3: Not shown in title block; Address4: Not shown in title block; DocumentNumber: 13; Revision: Use project parameter SCH_Rev; SheetNumber: 13; SheetTotal: 16; PageSetup: Record=PageOptions¦CenterHorizontal=True¦CenterVertical=True¦PrintScale=1.00¦XCorrection=1.00¦YCorrection=1.00¦PrintKind=0¦BorderSize=5000000¦LeftOffset=0¦BottomOffset=0¦Orientation=2¦PaperLength=1000¦PaperWidth=1000¦Scale=100¦PaperSource=15¦PrintQuality=600¦MediaType=1¦DitherType=10¦PaperKind=Letter¦PrintScaleMode=1
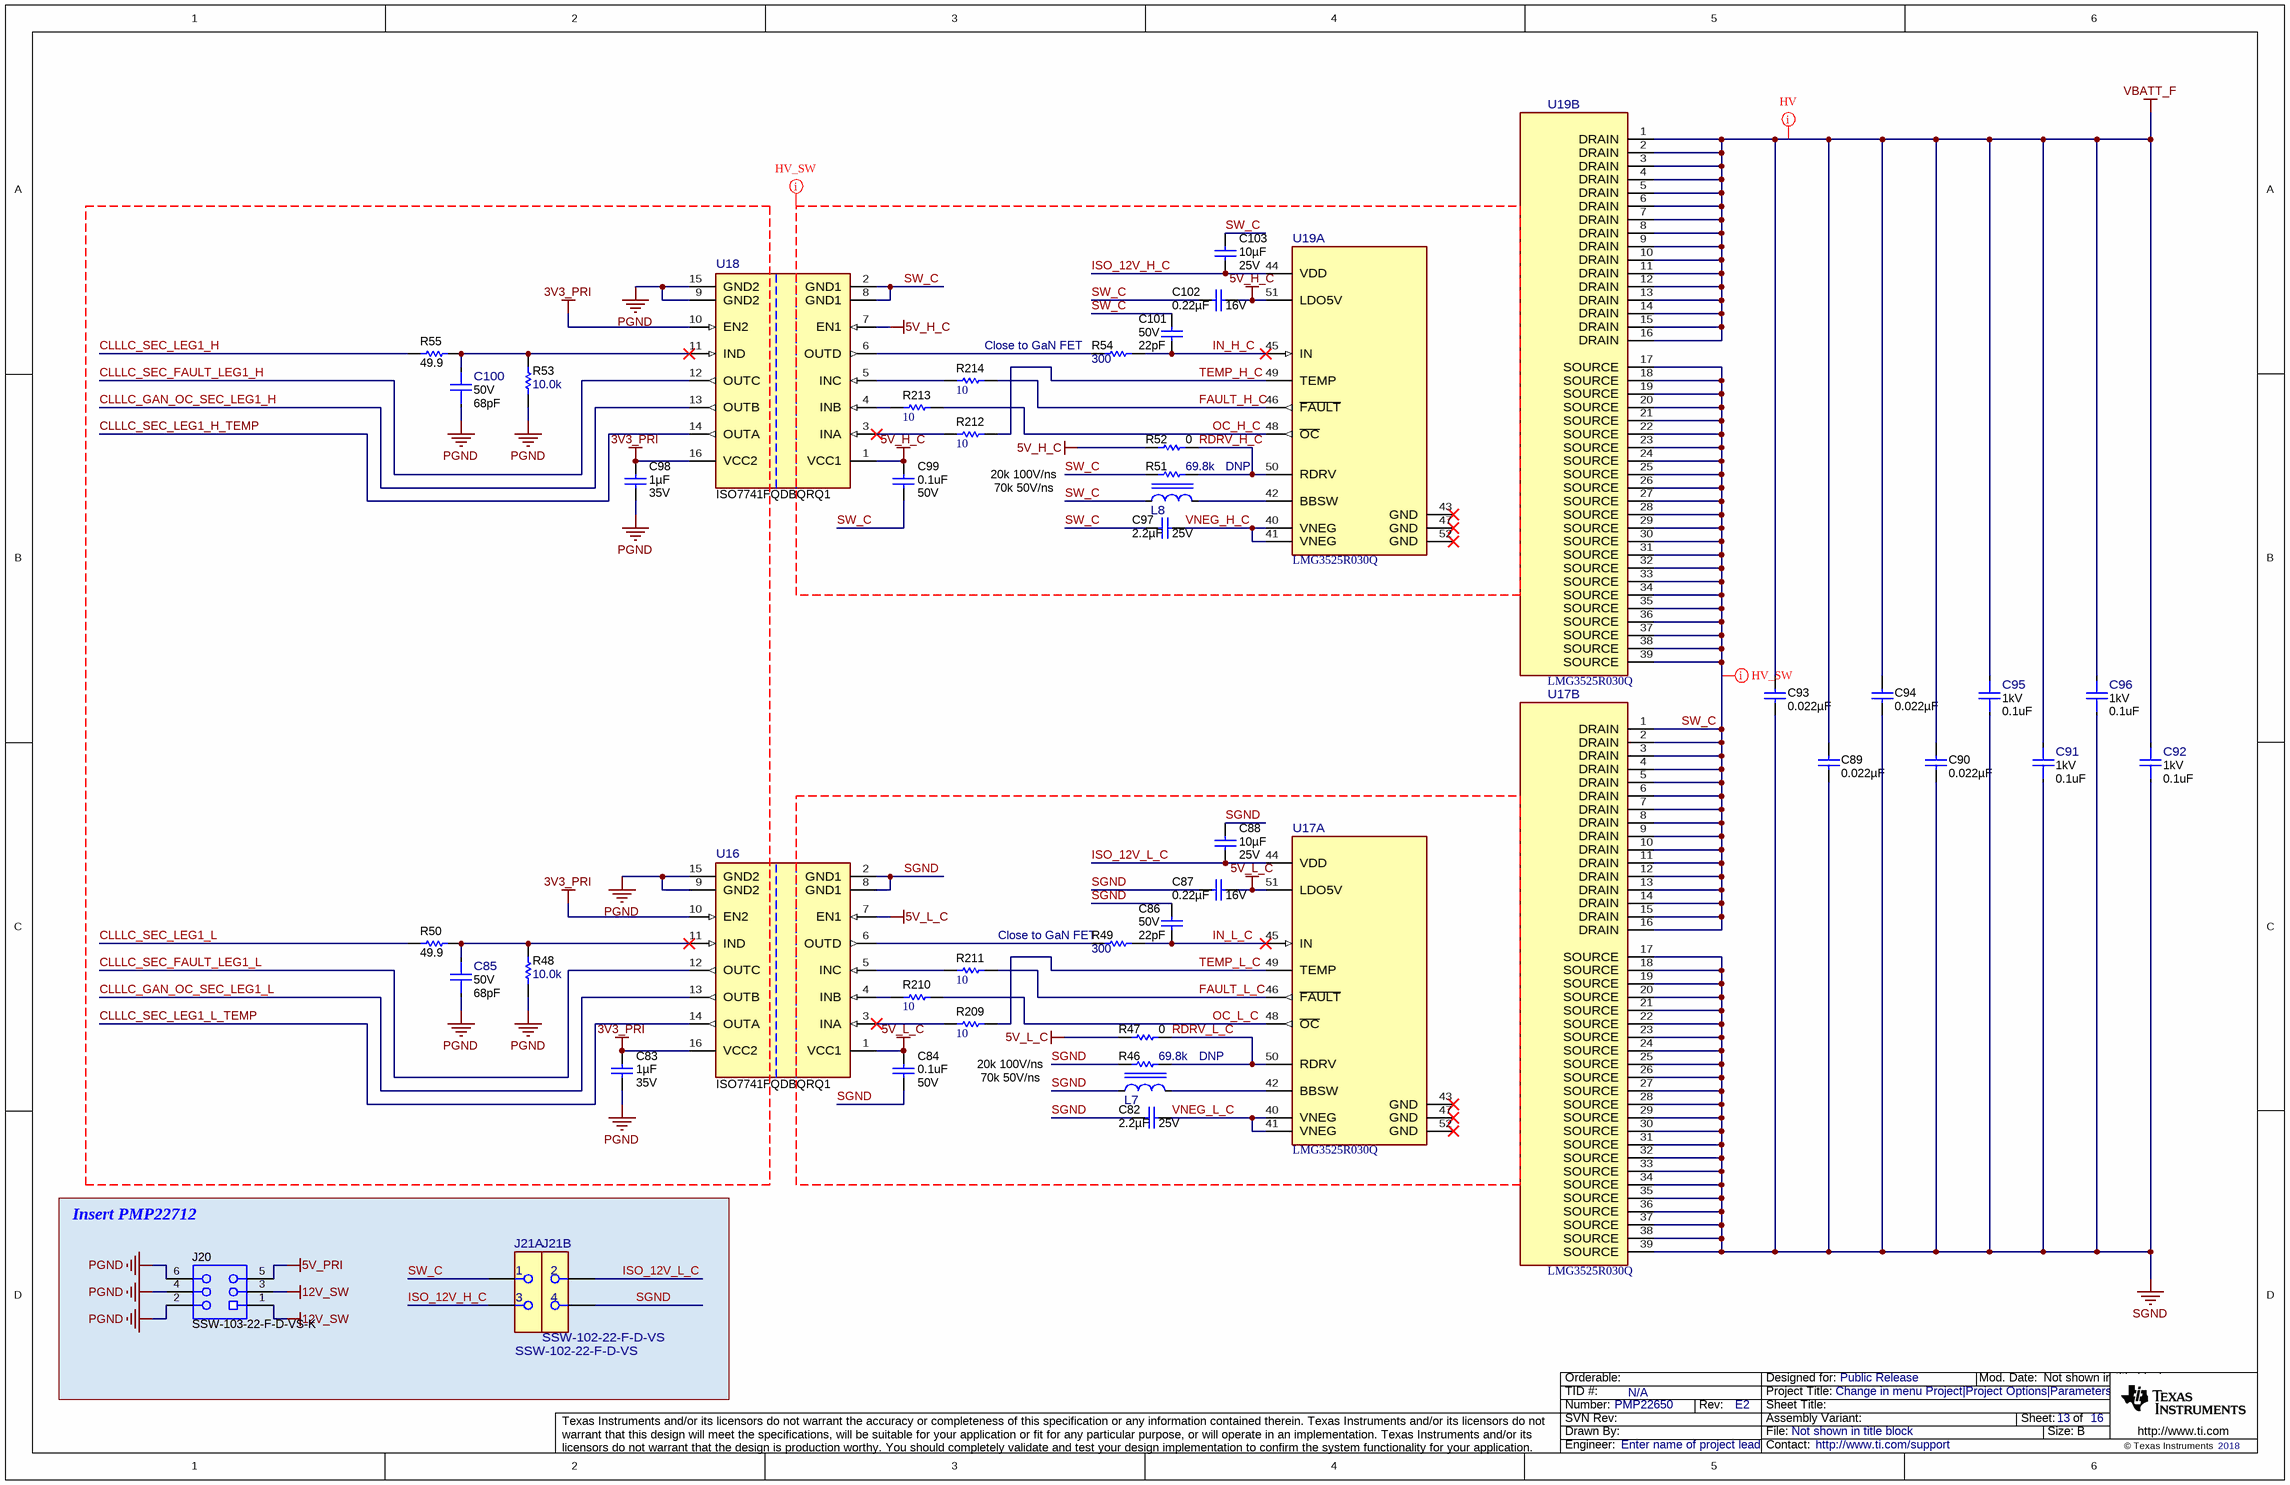
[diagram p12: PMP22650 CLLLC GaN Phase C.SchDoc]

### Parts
C82  Cap_F: 2.2µF  VDC_V: 25V  [0805_HV]  (hidden comment: CGA4J3X7R1E225K125AB)
C83  VDC_V: 35V  ValueDisplayed: 1µF  [0402]  (hidden comment: GRT155R6YA105KE13D)
C84  VDC_V: 50V  ValueDisplayed: 0.1uF  [0402]  (hidden comment: GCM155R71H104KE02D)
C85  VDC_V: 50V  ValueDisplayed: 68pF  [FP-GCM1555C1H680JA16D_0402-MFG]  (hidden comment: GCM1555C1H680JA16D)
C86  VDC_V: 50V  ValueDisplayed: 22pF  [0402]  (hidden comment: GCM1555C1H220JA16D)
C87  VDC_V: 16V  ValueDisplayed: 0.22µF  [0402]  (hidden comment: GCM155R71C224KE02D)
C88  VDC_V: 25V  ValueDisplayed: 10µF  [1206_180]  (hidden comment: TMK316AB7106KLHT)
C89  ValueDisplayed: 0.022µF  [1206_190]  (hidden comment: C1206C223KDRACTU)
C90  ValueDisplayed: 0.022µF  [1206_190]  (hidden comment: C1206C223KDRACTU)
C91  VDC_V: 1kV  ValueDisplayed: 0.1uF  [FP-C1812X104KDRACAUTO_1812-MFG]  (hidden comment: C1812X104KDRACAUTO)
C92  VDC_V: 1kV  ValueDisplayed: 0.1uF  [FP-C1812X104KDRACAUTO_1812-MFG]  (hidden comment: C1812X104KDRACAUTO)
C93  ValueDisplayed: 0.022µF  [1206_190]  (hidden comment: C1206C223KDRACTU)
C94  ValueDisplayed: 0.022µF  [1206_190]  (hidden comment: C1206C223KDRACTU)
C95  VDC_V: 1kV  ValueDisplayed: 0.1uF  [FP-C1812X104KDRACAUTO_1812-MFG]  (hidden comment: C1812X104KDRACAUTO)
C96  VDC_V: 1kV  ValueDisplayed: 0.1uF  [FP-C1812X104KDRACAUTO_1812-MFG]  (hidden comment: C1812X104KDRACAUTO)
C97  Cap_F: 2.2µF  VDC_V: 25V  [0805_HV]  (hidden comment: CGA4J3X7R1E225K125AB)
C98  VDC_V: 35V  ValueDisplayed: 1µF  [0402]  (hidden comment: GRT155R6YA105KE13D)
C99  VDC_V: 50V  ValueDisplayed: 0.1uF  [0402]  (hidden comment: GCM155R71H104KE02D)
C100  VDC_V: 50V  ValueDisplayed: 68pF  [FP-GCM1555C1H680JA16D_0402-MFG]  (hidden comment: GCM1555C1H680JA16D)
C101  VDC_V: 50V  ValueDisplayed: 22pF  [0402]  (hidden comment: GCM1555C1H220JA16D)
C102  VDC_V: 16V  ValueDisplayed: 0.22µF  [0402]  (hidden comment: GCM155R71C224KE02D)
C103  VDC_V: 25V  ValueDisplayed: 10µF  [1206_180]  (hidden comment: TMK316AB7106KLHT)
J20  SSW-103-22-F-D-VS-K  [SAMTEC_SSW-103-22-F-D-VS-K]
J21  SSW-102-22-F-D-VS  [FP-SSW-102-22-F-D-VS_RCPT4-MFG]  (parts A,B of 2)
L7  MPIA2510V2-4R7-R  [FP-MPIA2510V2-4R7-R_1008-MFG]  (value not drawn)
L8  MPIA2510V2-4R7-R  [FP-MPIA2510V2-4R7-R_1008-MFG]  (value not drawn)
R46  ValueDisplayed: 69.8k  [0402]  (hidden comment: CRCW040269K8FKED)
R47  ValueDisplayed: 0  [0402]  (hidden comment: ERJ-2GE0R00X)
R48  ValueDisplayed: 10.0k  [0402]  (hidden comment: CRCW040210K0FKED)
R49  ValueDisplayed: 300  [0402]  (hidden comment: CRCW0402300RJNED)
R50  ValueDisplayed: 49.9  [0402]  (hidden comment: CRCW040249R9FKED)
R51  ValueDisplayed: 69.8k  [0402]  (hidden comment: CRCW040269K8FKED)
R52  ValueDisplayed: 0  [0402]  (hidden comment: ERJ-2GE0R00X)
R53  ValueDisplayed: 10.0k  [0402]  (hidden comment: CRCW040210K0FKED)
R54  ValueDisplayed: 300  [0402]  (hidden comment: CRCW0402300RJNED)
R55  ValueDisplayed: 49.9  [0402]  (hidden comment: CRCW040249R9FKED)
R209  ValueDisplayed: 10  [0402]  (hidden comment: CRCW040210R0JNED)
R210  ValueDisplayed: 10  [0402]  (hidden comment: CRCW040210R0JNED)
R211  ValueDisplayed: 10  [0402]  (hidden comment: CRCW040210R0JNED)
R212  ValueDisplayed: 10  [0402]  (hidden comment: CRCW040210R0JNED)
R213  ValueDisplayed: 10  [0402]  (hidden comment: CRCW040210R0JNED)
R214  ValueDisplayed: 10  [0402]  (hidden comment: CRCW040210R0JNED)
U16  ISO7741FQDBQRQ1  [DBQ0016A-MFG]
U17  LMG3525R030Q  [RQS0052A-MFG]  (parts A,B of 2)
U18  ISO7741FQDBQRQ1  [DBQ0016A-MFG]
U19  LMG3525R030Q  [RQS0052A-MFG]  (parts A,B of 2)

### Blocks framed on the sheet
Insert PMP22712: J20 J21

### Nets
3V3_PRI: C83.1 C98.1 U16.10(EN2) U16.16(VCC2) U18.10(EN2) U18.16(VCC2)
5V_H_C: C99.1 C102.1 R52.2 U18.1(VCC1) U18.7(EN1) U19.51(LDO5V)
5V_L_C: C84.1 C87.1 R47.2 U16.1(VCC1) U16.7(EN1) U17.51(LDO5V)
5V_PRI: J20.5
12V_SW: J20.1 J20.3
PGND: C83.2 C85.1 C98.2 C100.1 J20.2 J20.4 J20.6 R48.1 R53.1 U16.9(GND2) U16.15(GND2) U18.9(GND2) U18.15(GND2)
SGND: C82.1 C84.2 C86.1 C87.2 C88.2 C89.2 C90.2 C91.1 C92.1 C93.2 C94.2 C95.1 C96.1 J21.4 L7.1 R46.1 U16.2(GND1) U16.8(GND1) U17.17(SOURCE) U17.18(SOURCE) U17.19(SOURCE) U17.20(SOURCE) U17.21(SOURCE) U17.22(SOURCE) U17.23(SOURCE) U17.24(SOURCE) U17.25(SOURCE) U17.26(SOURCE) U17.27(SOURCE) U17.28(SOURCE) U17.29(SOURCE) U17.30(SOURCE) U17.31(SOURCE) U17.32(SOURCE) U17.33(SOURCE) U17.34(SOURCE) U17.35(SOURCE) U17.36(SOURCE) U17.37(SOURCE) U17.38(SOURCE) U17.39(SOURCE)
VBATT_F: C89.1 C90.1 C91.2 C92.2 C93.1 C94.1 C95.2 C96.2 U19.1(DRAIN) U19.2(DRAIN) U19.3(DRAIN) U19.4(DRAIN) U19.5(DRAIN) U19.6(DRAIN) U19.7(DRAIN) U19.8(DRAIN) U19.9(DRAIN) U19.10(DRAIN) U19.11(DRAIN) U19.12(DRAIN) U19.13(DRAIN) U19.14(DRAIN) U19.15(DRAIN) U19.16(DRAIN)
CLLLC_GAN_OC_SEC_LEG1_H: U18.13(OUTB)
CLLLC_GAN_OC_SEC_LEG1_L: U16.13(OUTB)
CLLLC_SEC_FAULT_LEG1_H: U18.12(OUTC)
CLLLC_SEC_FAULT_LEG1_L: U16.12(OUTC)
CLLLC_SEC_LEG1_H: R55.1
CLLLC_SEC_LEG1_H_TEMP: U18.14(OUTA)
CLLLC_SEC_LEG1_L: R50.1
CLLLC_SEC_LEG1_L_TEMP: U16.14(OUTA)
FAULT_H_C: R214.2 U19.46(~{FAULT})
FAULT_L_C: R211.2 U17.46(~{FAULT})
IN_H_C: C101.2 R54.2 U19.45(IN)
IN_L_C: C86.2 R49.2 U17.45(IN)
ISO_12V_H_C: C103.1 J21.3 U19.44(VDD)
ISO_12V_L_C: C88.1 J21.2 U17.44(VDD)
OC_H_C: R213.2 U19.48(~{OC})
OC_L_C: R210.2 U17.48(~{OC})
RDRV_H_C: R51.2 R52.1 U19.50(RDRV)
RDRV_L_C: R46.2 R47.1 U17.50(RDRV)
SW_C: C97.1 C99.2 C101.1 C102.2 C103.2 J21.1 L8.1 R51.1 U17.1(DRAIN) U17.2(DRAIN) U17.3(DRAIN) U17.4(DRAIN) U17.5(DRAIN) U17.6(DRAIN) U17.7(DRAIN) U17.8(DRAIN) U17.9(DRAIN) U17.10(DRAIN) U17.11(DRAIN) U17.12(DRAIN) U17.13(DRAIN) U17.14(DRAIN) U17.15(DRAIN) U17.16(DRAIN) U18.2(GND1) U18.8(GND1) U19.17(SOURCE) U19.18(SOURCE) U19.19(SOURCE) U19.20(SOURCE) U19.21(SOURCE) U19.22(SOURCE) U19.23(SOURCE) U19.24(SOURCE) U19.25(SOURCE) U19.26(SOURCE) U19.27(SOURCE) U19.28(SOURCE) U19.29(SOURCE) U19.30(SOURCE) U19.31(SOURCE) U19.32(SOURCE) U19.33(SOURCE) U19.34(SOURCE) U19.35(SOURCE) U19.36(SOURCE) U19.37(SOURCE) U19.38(SOURCE) U19.39(SOURCE)
TEMP_H_C: R212.2 U19.49(TEMP)
TEMP_L_C: R209.2 U17.49(TEMP)
VNEG_H_C: C97.2 U19.40(VNEG) U19.41(VNEG)
VNEG_L_C: C82.2 U17.40(VNEG) U17.41(VNEG)
NetC85_2: C85.2 R48.2 R50.2 U16.11(IND)
NetC100_2: C100.2 R53.2 R55.2 U18.11(IND)
NetL7_2: L7.2 U17.42(BBSW)
NetL8_2: L8.2 U19.42(BBSW)
NetR49_1: R49.1 U16.6(OUTD)
NetR54_1: R54.1 U18.6(OUTD)
NetR209_1: R209.1 U16.3(INA)
NetR210_1: R210.1 U16.4(INB)
NetR211_1: R211.1 U16.5(INC)
NetR212_1: R212.1 U18.3(INA)
NetR213_1: R213.1 U18.4(INB)
NetR214_1: R214.1 U18.5(INC)

Not connected (* = marked no-connect by the designer): U17 43(GND)* 47(GND)* 52(GND)*; U19 43(GND)* 47(GND)* 52(GND)*

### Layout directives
net class HV_SW: 5V_H_C, FAULT_H_C, IN_H_C, ISO_12V_H_C, OC_H_C, RDRV_H_C, SW_C, TEMP_H_C, VNEG_H_C
net class HV: VBATT_F

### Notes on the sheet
- Close to GaN FET
- (near R212) 20k 100V/ns
- (near R212) 70k 50V/ns
- DNP
- (near R49) Close to GaN FET
- (near R209) 20k 100V/ns
- (near R209) 70k 50V/ns

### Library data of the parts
C82 C97 = CMP-0007975-2: as C38 on sheet PMP22650 CLLLC GaN Phase A
C83 C98 = CMP-0750099-1: as C39 on sheet PMP22650 CLLLC GaN Phase A
C84 C99 = CMP-0006356-2: as C40 on sheet PMP22650 CLLLC GaN Phase A
C85 C100 = CMP-0090521-1: as C41 on sheet PMP22650 CLLLC GaN Phase A
C86 C101 = CMP-0006348-2: as C42 on sheet PMP22650 CLLLC GaN Phase A
C87 C102 = CMP-0078265-1: as C43 on sheet PMP22650 CLLLC GaN Phase A
C88 C103 = CMP-0750154-1: as C44 on sheet PMP22650 CLLLC GaN Phase A
C89 C90 C93 C94 = CMP-0084048-1: as C256 on sheet PMP22650 CLLLC Power Stage
C91 C92 C95 C96 = CMP-0090548-1: as C47 on sheet PMP22650 CLLLC GaN Phase A
J20 = CMP-0055666-1: as J12 on sheet PMP22650 CLLLC Power Stage
J21 = CMP-0090790-1: as J17 on sheet PMP22650 CLLLC GaN Phase A
L7 L8 = CMP-0090507-1: as L3 on sheet PMP22650 CLLLC GaN Phase A
R46 R51 = CMP-0026510-2: as R26 on sheet PMP22650 CLLLC GaN Phase A
R47 R52 = CMP-0026992-3: as R27 on sheet PMP22650 CLLLC GaN Phase A
R48 R53 = CMP-0025958-3: as R28 on sheet PMP22650 CLLLC GaN Phase A
R49 R54 = CMP-0026902-3: as R29 on sheet PMP22650 CLLLC GaN Phase A
R50 R55 = CMP-0026404-2: as R30 on sheet PMP22650 CLLLC GaN Phase A
R209-R214 = CMP-0026827-3: RES, 10, 5%, 0.063 W, AEC-Q200 Grade 0, 0402; Manufacturer: Vishay-Dale; Power_W: 63mW; TempCo: 200 ppm/C; Value_Code: 10R0; Value: 10; EIA_Code: E24; SizeX_mm: 1; SizeY_mm: 0.5; SizeZ_mm: 0.6; Value2: 0.063W; AEC Qualified: Y; VDC_V: 50V; AEC Category: Q200; AEC Grade: 0
U16 U18 = CMP-0090469-1: as U8 on sheet PMP22650 CLLLC GaN Phase A
U17 U19 = CMP-0089968-2: as U9 on sheet PMP22650 CLLLC GaN Phase A

## Sheet PMP22650 CLLLC GaN Phase D.SchDoc
size 431 x 279 mm; Date: Not shown in title block; ApprovedBy: Not shown in title block; CheckedBy: Not shown in title block; Author: Not shown in title block; CompanyName: Not shown in title block; Engineer: Not shown in title block; Organization: Not shown in title block; Address1: Not shown in title block; Address2: Not shown in title block; Address3: Not shown in title block; Address4: Not shown in title block; DocumentNumber: 14; Revision: Use project parameter SCH_Rev; SheetNumber: 14; SheetTotal: 16; PageSetup: Record=PageOptions¦CenterHorizontal=True¦CenterVertical=True¦PrintScale=1.00¦XCorrection=1.00¦YCorrection=1.00¦PrintKind=0¦BorderSize=5000000¦LeftOffset=0¦BottomOffset=0¦Orientation=2¦PaperLength=1000¦PaperWidth=1000¦Scale=100¦PaperSource=15¦PrintQuality=600¦MediaType=1¦DitherType=10¦PaperKind=Letter¦PrintScaleMode=1
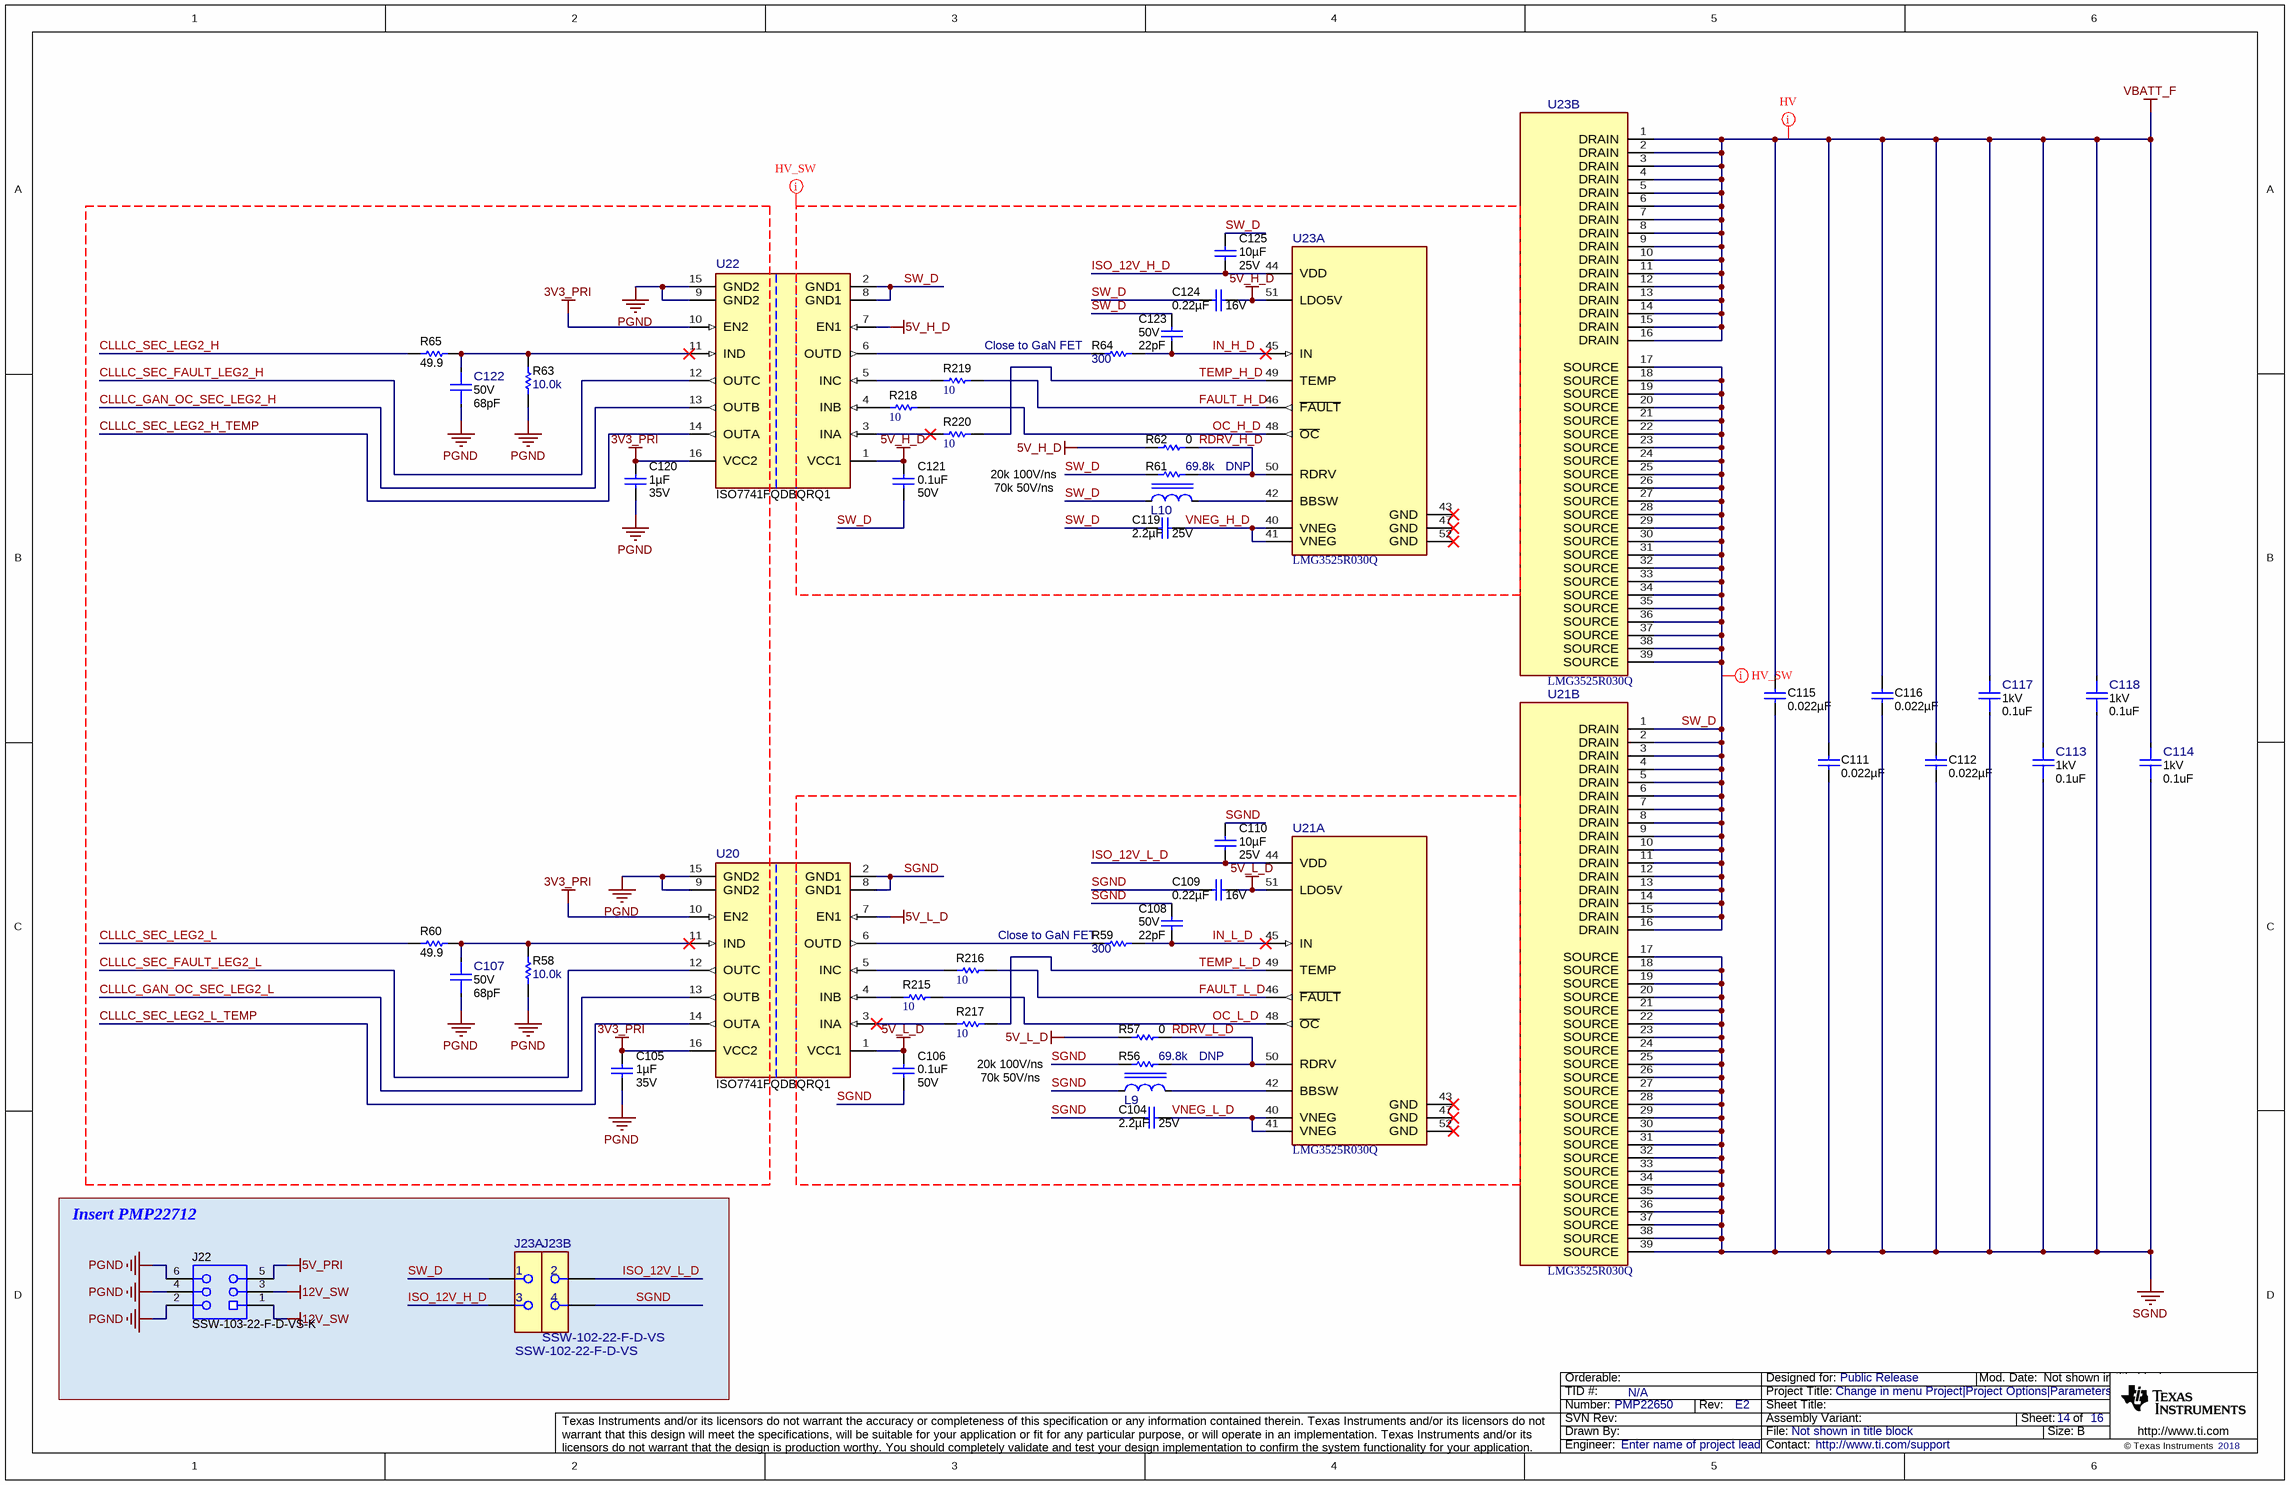
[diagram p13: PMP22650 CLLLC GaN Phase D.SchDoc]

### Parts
C104  Cap_F: 2.2µF  VDC_V: 25V  [0805_HV]  (hidden comment: CGA4J3X7R1E225K125AB)
C105  VDC_V: 35V  ValueDisplayed: 1µF  [0402]  (hidden comment: GRT155R6YA105KE13D)
C106  VDC_V: 50V  ValueDisplayed: 0.1uF  [0402]  (hidden comment: GCM155R71H104KE02D)
C107  VDC_V: 50V  ValueDisplayed: 68pF  [FP-GCM1555C1H680JA16D_0402-MFG]  (hidden comment: GCM1555C1H680JA16D)
C108  VDC_V: 50V  ValueDisplayed: 22pF  [0402]  (hidden comment: GCM1555C1H220JA16D)
C109  VDC_V: 16V  ValueDisplayed: 0.22µF  [0402]  (hidden comment: GCM155R71C224KE02D)
C110  VDC_V: 25V  ValueDisplayed: 10µF  [1206_180]  (hidden comment: TMK316AB7106KLHT)
C111  ValueDisplayed: 0.022µF  [1206_190]  (hidden comment: C1206C223KDRACTU)
C112  ValueDisplayed: 0.022µF  [1206_190]  (hidden comment: C1206C223KDRACTU)
C113  VDC_V: 1kV  ValueDisplayed: 0.1uF  [FP-C1812X104KDRACAUTO_1812-MFG]  (hidden comment: C1812X104KDRACAUTO)
C114  VDC_V: 1kV  ValueDisplayed: 0.1uF  [FP-C1812X104KDRACAUTO_1812-MFG]  (hidden comment: C1812X104KDRACAUTO)
C115  ValueDisplayed: 0.022µF  [1206_190]  (hidden comment: C1206C223KDRACTU)
C116  ValueDisplayed: 0.022µF  [1206_190]  (hidden comment: C1206C223KDRACTU)
C117  VDC_V: 1kV  ValueDisplayed: 0.1uF  [FP-C1812X104KDRACAUTO_1812-MFG]  (hidden comment: C1812X104KDRACAUTO)
C118  VDC_V: 1kV  ValueDisplayed: 0.1uF  [FP-C1812X104KDRACAUTO_1812-MFG]  (hidden comment: C1812X104KDRACAUTO)
C119  Cap_F: 2.2µF  VDC_V: 25V  [0805_HV]  (hidden comment: CGA4J3X7R1E225K125AB)
C120  VDC_V: 35V  ValueDisplayed: 1µF  [0402]  (hidden comment: GRT155R6YA105KE13D)
C121  VDC_V: 50V  ValueDisplayed: 0.1uF  [0402]  (hidden comment: GCM155R71H104KE02D)
C122  VDC_V: 50V  ValueDisplayed: 68pF  [FP-GCM1555C1H680JA16D_0402-MFG]  (hidden comment: GCM1555C1H680JA16D)
C123  VDC_V: 50V  ValueDisplayed: 22pF  [0402]  (hidden comment: GCM1555C1H220JA16D)
C124  VDC_V: 16V  ValueDisplayed: 0.22µF  [0402]  (hidden comment: GCM155R71C224KE02D)
C125  VDC_V: 25V  ValueDisplayed: 10µF  [1206_180]  (hidden comment: TMK316AB7106KLHT)
J22  SSW-103-22-F-D-VS-K  [SAMTEC_SSW-103-22-F-D-VS-K]
J23  SSW-102-22-F-D-VS  [FP-SSW-102-22-F-D-VS_RCPT4-MFG]  (parts A,B of 2)
L9  MPIA2510V2-4R7-R  [FP-MPIA2510V2-4R7-R_1008-MFG]  (value not drawn)
L10  MPIA2510V2-4R7-R  [FP-MPIA2510V2-4R7-R_1008-MFG]  (value not drawn)
R56  ValueDisplayed: 69.8k  [0402]  (hidden comment: CRCW040269K8FKED)
R57  ValueDisplayed: 0  [0402]  (hidden comment: ERJ-2GE0R00X)
R58  ValueDisplayed: 10.0k  [0402]  (hidden comment: CRCW040210K0FKED)
R59  ValueDisplayed: 300  [0402]  (hidden comment: CRCW0402300RJNED)
R60  ValueDisplayed: 49.9  [0402]  (hidden comment: CRCW040249R9FKED)
R61  ValueDisplayed: 69.8k  [0402]  (hidden comment: CRCW040269K8FKED)
R62  ValueDisplayed: 0  [0402]  (hidden comment: ERJ-2GE0R00X)
R63  ValueDisplayed: 10.0k  [0402]  (hidden comment: CRCW040210K0FKED)
R64  ValueDisplayed: 300  [0402]  (hidden comment: CRCW0402300RJNED)
R65  ValueDisplayed: 49.9  [0402]  (hidden comment: CRCW040249R9FKED)
R215  ValueDisplayed: 10  [0402]  (hidden comment: CRCW040210R0JNED)
R216  ValueDisplayed: 10  [0402]  (hidden comment: CRCW040210R0JNED)
R217  ValueDisplayed: 10  [0402]  (hidden comment: CRCW040210R0JNED)
R218  ValueDisplayed: 10  [0402]  (hidden comment: CRCW040210R0JNED)
R219  ValueDisplayed: 10  [0402]  (hidden comment: CRCW040210R0JNED)
R220  ValueDisplayed: 10  [0402]  (hidden comment: CRCW040210R0JNED)
U20  ISO7741FQDBQRQ1  [DBQ0016A-MFG]
U21  LMG3525R030Q  [RQS0052A-MFG]  (parts A,B of 2)
U22  ISO7741FQDBQRQ1  [DBQ0016A-MFG]
U23  LMG3525R030Q  [RQS0052A-MFG]  (parts A,B of 2)

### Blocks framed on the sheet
Insert PMP22712: J22 J23

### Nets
3V3_PRI: C105.1 C120.1 U20.10(EN2) U20.16(VCC2) U22.10(EN2) U22.16(VCC2)
5V_H_D: C121.1 C124.1 R62.2 U22.1(VCC1) U22.7(EN1) U23.51(LDO5V)
5V_L_D: C106.1 C109.1 R57.2 U20.1(VCC1) U20.7(EN1) U21.51(LDO5V)
5V_PRI: J22.5
12V_SW: J22.1 J22.3
PGND: C105.2 C107.1 C120.2 C122.1 J22.2 J22.4 J22.6 R58.1 R63.1 U20.9(GND2) U20.15(GND2) U22.9(GND2) U22.15(GND2)
SGND: C104.1 C106.2 C108.1 C109.2 C110.2 C111.2 C112.2 C113.1 C114.1 C115.2 C116.2 C117.1 C118.1 J23.4 L9.1 R56.1 U20.2(GND1) U20.8(GND1) U21.17(SOURCE) U21.18(SOURCE) U21.19(SOURCE) U21.20(SOURCE) U21.21(SOURCE) U21.22(SOURCE) U21.23(SOURCE) U21.24(SOURCE) U21.25(SOURCE) U21.26(SOURCE) U21.27(SOURCE) U21.28(SOURCE) U21.29(SOURCE) U21.30(SOURCE) U21.31(SOURCE) U21.32(SOURCE) U21.33(SOURCE) U21.34(SOURCE) U21.35(SOURCE) U21.36(SOURCE) U21.37(SOURCE) U21.38(SOURCE) U21.39(SOURCE)
VBATT_F: C111.1 C112.1 C113.2 C114.2 C115.1 C116.1 C117.2 C118.2 U23.1(DRAIN) U23.2(DRAIN) U23.3(DRAIN) U23.4(DRAIN) U23.5(DRAIN) U23.6(DRAIN) U23.7(DRAIN) U23.8(DRAIN) U23.9(DRAIN) U23.10(DRAIN) U23.11(DRAIN) U23.12(DRAIN) U23.13(DRAIN) U23.14(DRAIN) U23.15(DRAIN) U23.16(DRAIN)
CLLLC_GAN_OC_SEC_LEG2_H: U22.13(OUTB)
CLLLC_GAN_OC_SEC_LEG2_L: U20.13(OUTB)
CLLLC_SEC_FAULT_LEG2_H: U22.12(OUTC)
CLLLC_SEC_FAULT_LEG2_L: U20.12(OUTC)
CLLLC_SEC_LEG2_H: R65.1
CLLLC_SEC_LEG2_H_TEMP: U22.14(OUTA)
CLLLC_SEC_LEG2_L: R60.1
CLLLC_SEC_LEG2_L_TEMP: U20.14(OUTA)
FAULT_H_D: R219.2 U23.46(~{FAULT})
FAULT_L_D: R216.2 U21.46(~{FAULT})
IN_H_D: C123.2 R64.2 U23.45(IN)
IN_L_D: C108.2 R59.2 U21.45(IN)
ISO_12V_H_D: C125.1 J23.3 U23.44(VDD)
ISO_12V_L_D: C110.1 J23.2 U21.44(VDD)
OC_H_D: R218.2 U23.48(~{OC})
OC_L_D: R215.2 U21.48(~{OC})
RDRV_H_D: R61.2 R62.1 U23.50(RDRV)
RDRV_L_D: R56.2 R57.1 U21.50(RDRV)
SW_D: C119.1 C121.2 C123.1 C124.2 C125.2 J23.1 L10.1 R61.1 U21.1(DRAIN) U21.2(DRAIN) U21.3(DRAIN) U21.4(DRAIN) U21.5(DRAIN) U21.6(DRAIN) U21.7(DRAIN) U21.8(DRAIN) U21.9(DRAIN) U21.10(DRAIN) U21.11(DRAIN) U21.12(DRAIN) U21.13(DRAIN) U21.14(DRAIN) U21.15(DRAIN) U21.16(DRAIN) U22.2(GND1) U22.8(GND1) U23.17(SOURCE) U23.18(SOURCE) U23.19(SOURCE) U23.20(SOURCE) U23.21(SOURCE) U23.22(SOURCE) U23.23(SOURCE) U23.24(SOURCE) U23.25(SOURCE) U23.26(SOURCE) U23.27(SOURCE) U23.28(SOURCE) U23.29(SOURCE) U23.30(SOURCE) U23.31(SOURCE) U23.32(SOURCE) U23.33(SOURCE) U23.34(SOURCE) U23.35(SOURCE) U23.36(SOURCE) U23.37(SOURCE) U23.38(SOURCE) U23.39(SOURCE)
TEMP_H_D: R220.2 U23.49(TEMP)
TEMP_L_D: R217.2 U21.49(TEMP)
VNEG_H_D: C119.2 U23.40(VNEG) U23.41(VNEG)
VNEG_L_D: C104.2 U21.40(VNEG) U21.41(VNEG)
NetC107_2: C107.2 R58.2 R60.2 U20.11(IND)
NetC122_2: C122.2 R63.2 R65.2 U22.11(IND)
NetL9_2: L9.2 U21.42(BBSW)
NetL10_2: L10.2 U23.42(BBSW)
NetR59_1: R59.1 U20.6(OUTD)
NetR64_1: R64.1 U22.6(OUTD)
NetR215_1: R215.1 U20.4(INB)
NetR216_1: R216.1 U20.5(INC)
NetR217_1: R217.1 U20.3(INA)
NetR218_1: R218.1 U22.4(INB)
NetR219_1: R219.1 U22.5(INC)
NetR220_1: R220.1 U22.3(INA)

Not connected (* = marked no-connect by the designer): U21 43(GND)* 47(GND)* 52(GND)*; U23 43(GND)* 47(GND)* 52(GND)*

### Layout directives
net class HV_SW: 5V_H_D, FAULT_H_D, IN_H_D, ISO_12V_H_D, OC_H_D, RDRV_H_D, SW_D, TEMP_H_D, VNEG_H_D
net class HV: VBATT_F

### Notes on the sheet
- Close to GaN FET
- (near R220) 20k 100V/ns
- (near R220) 70k 50V/ns
- DNP
- (near R59) Close to GaN FET
- (near R217) 20k 100V/ns
- (near R217) 70k 50V/ns

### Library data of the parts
C104 C119 = CMP-0007975-2: as C38 on sheet PMP22650 CLLLC GaN Phase A
C105 C120 = CMP-0750099-1: as C39 on sheet PMP22650 CLLLC GaN Phase A
C106 C121 = CMP-0006356-2: as C40 on sheet PMP22650 CLLLC GaN Phase A
C107 C122 = CMP-0090521-1: as C41 on sheet PMP22650 CLLLC GaN Phase A
C108 C123 = CMP-0006348-2: as C42 on sheet PMP22650 CLLLC GaN Phase A
C109 C124 = CMP-0078265-1: as C43 on sheet PMP22650 CLLLC GaN Phase A
C110 C125 = CMP-0750154-1: as C44 on sheet PMP22650 CLLLC GaN Phase A
C111 C112 C115 C116 = CMP-0084048-1: as C256 on sheet PMP22650 CLLLC Power Stage
C113 C114 C117 C118 = CMP-0090548-1: as C47 on sheet PMP22650 CLLLC GaN Phase A
J22 = CMP-0055666-1: as J12 on sheet PMP22650 CLLLC Power Stage
J23 = CMP-0090790-1: as J17 on sheet PMP22650 CLLLC GaN Phase A
L9 L10 = CMP-0090507-1: as L3 on sheet PMP22650 CLLLC GaN Phase A
R56 R61 = CMP-0026510-2: as R26 on sheet PMP22650 CLLLC GaN Phase A
R57 R62 = CMP-0026992-3: as R27 on sheet PMP22650 CLLLC GaN Phase A
R58 R63 = CMP-0025958-3: as R28 on sheet PMP22650 CLLLC GaN Phase A
R59 R64 = CMP-0026902-3: as R29 on sheet PMP22650 CLLLC GaN Phase A
R60 R65 = CMP-0026404-2: as R30 on sheet PMP22650 CLLLC GaN Phase A
R215-R220 = CMP-0026827-3: as R209 on sheet PMP22650 CLLLC GaN Phase C
U20 U22 = CMP-0090469-1: as U8 on sheet PMP22650 CLLLC GaN Phase A
U21 U23 = CMP-0089968-2: as U9 on sheet PMP22650 CLLLC GaN Phase A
